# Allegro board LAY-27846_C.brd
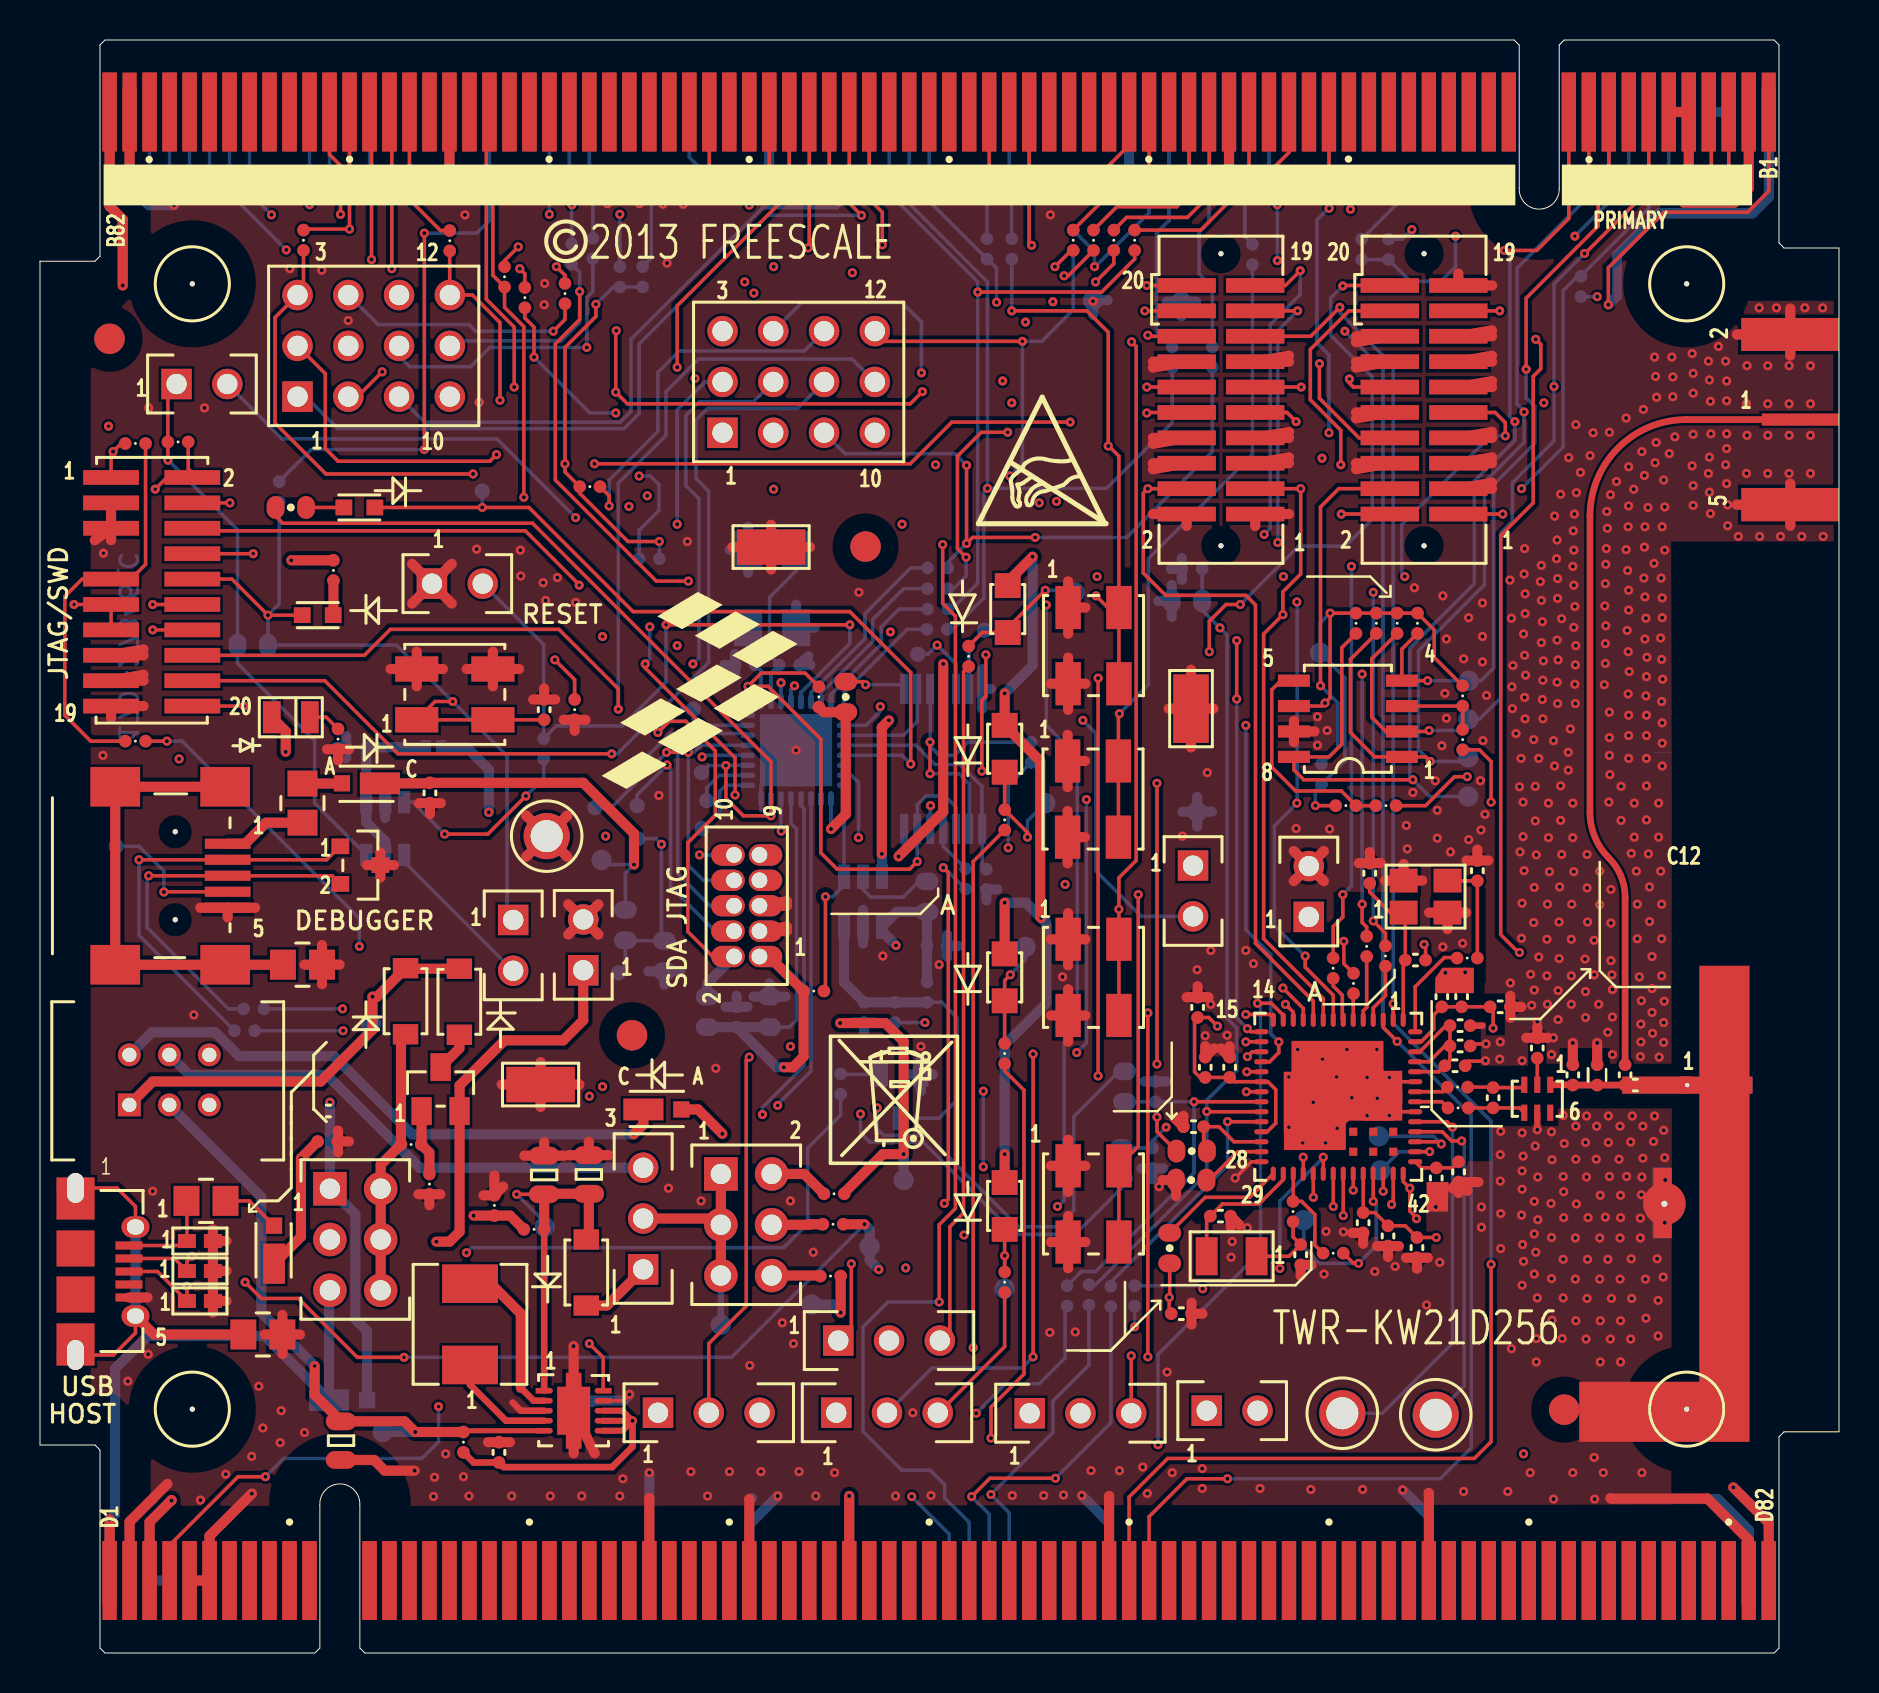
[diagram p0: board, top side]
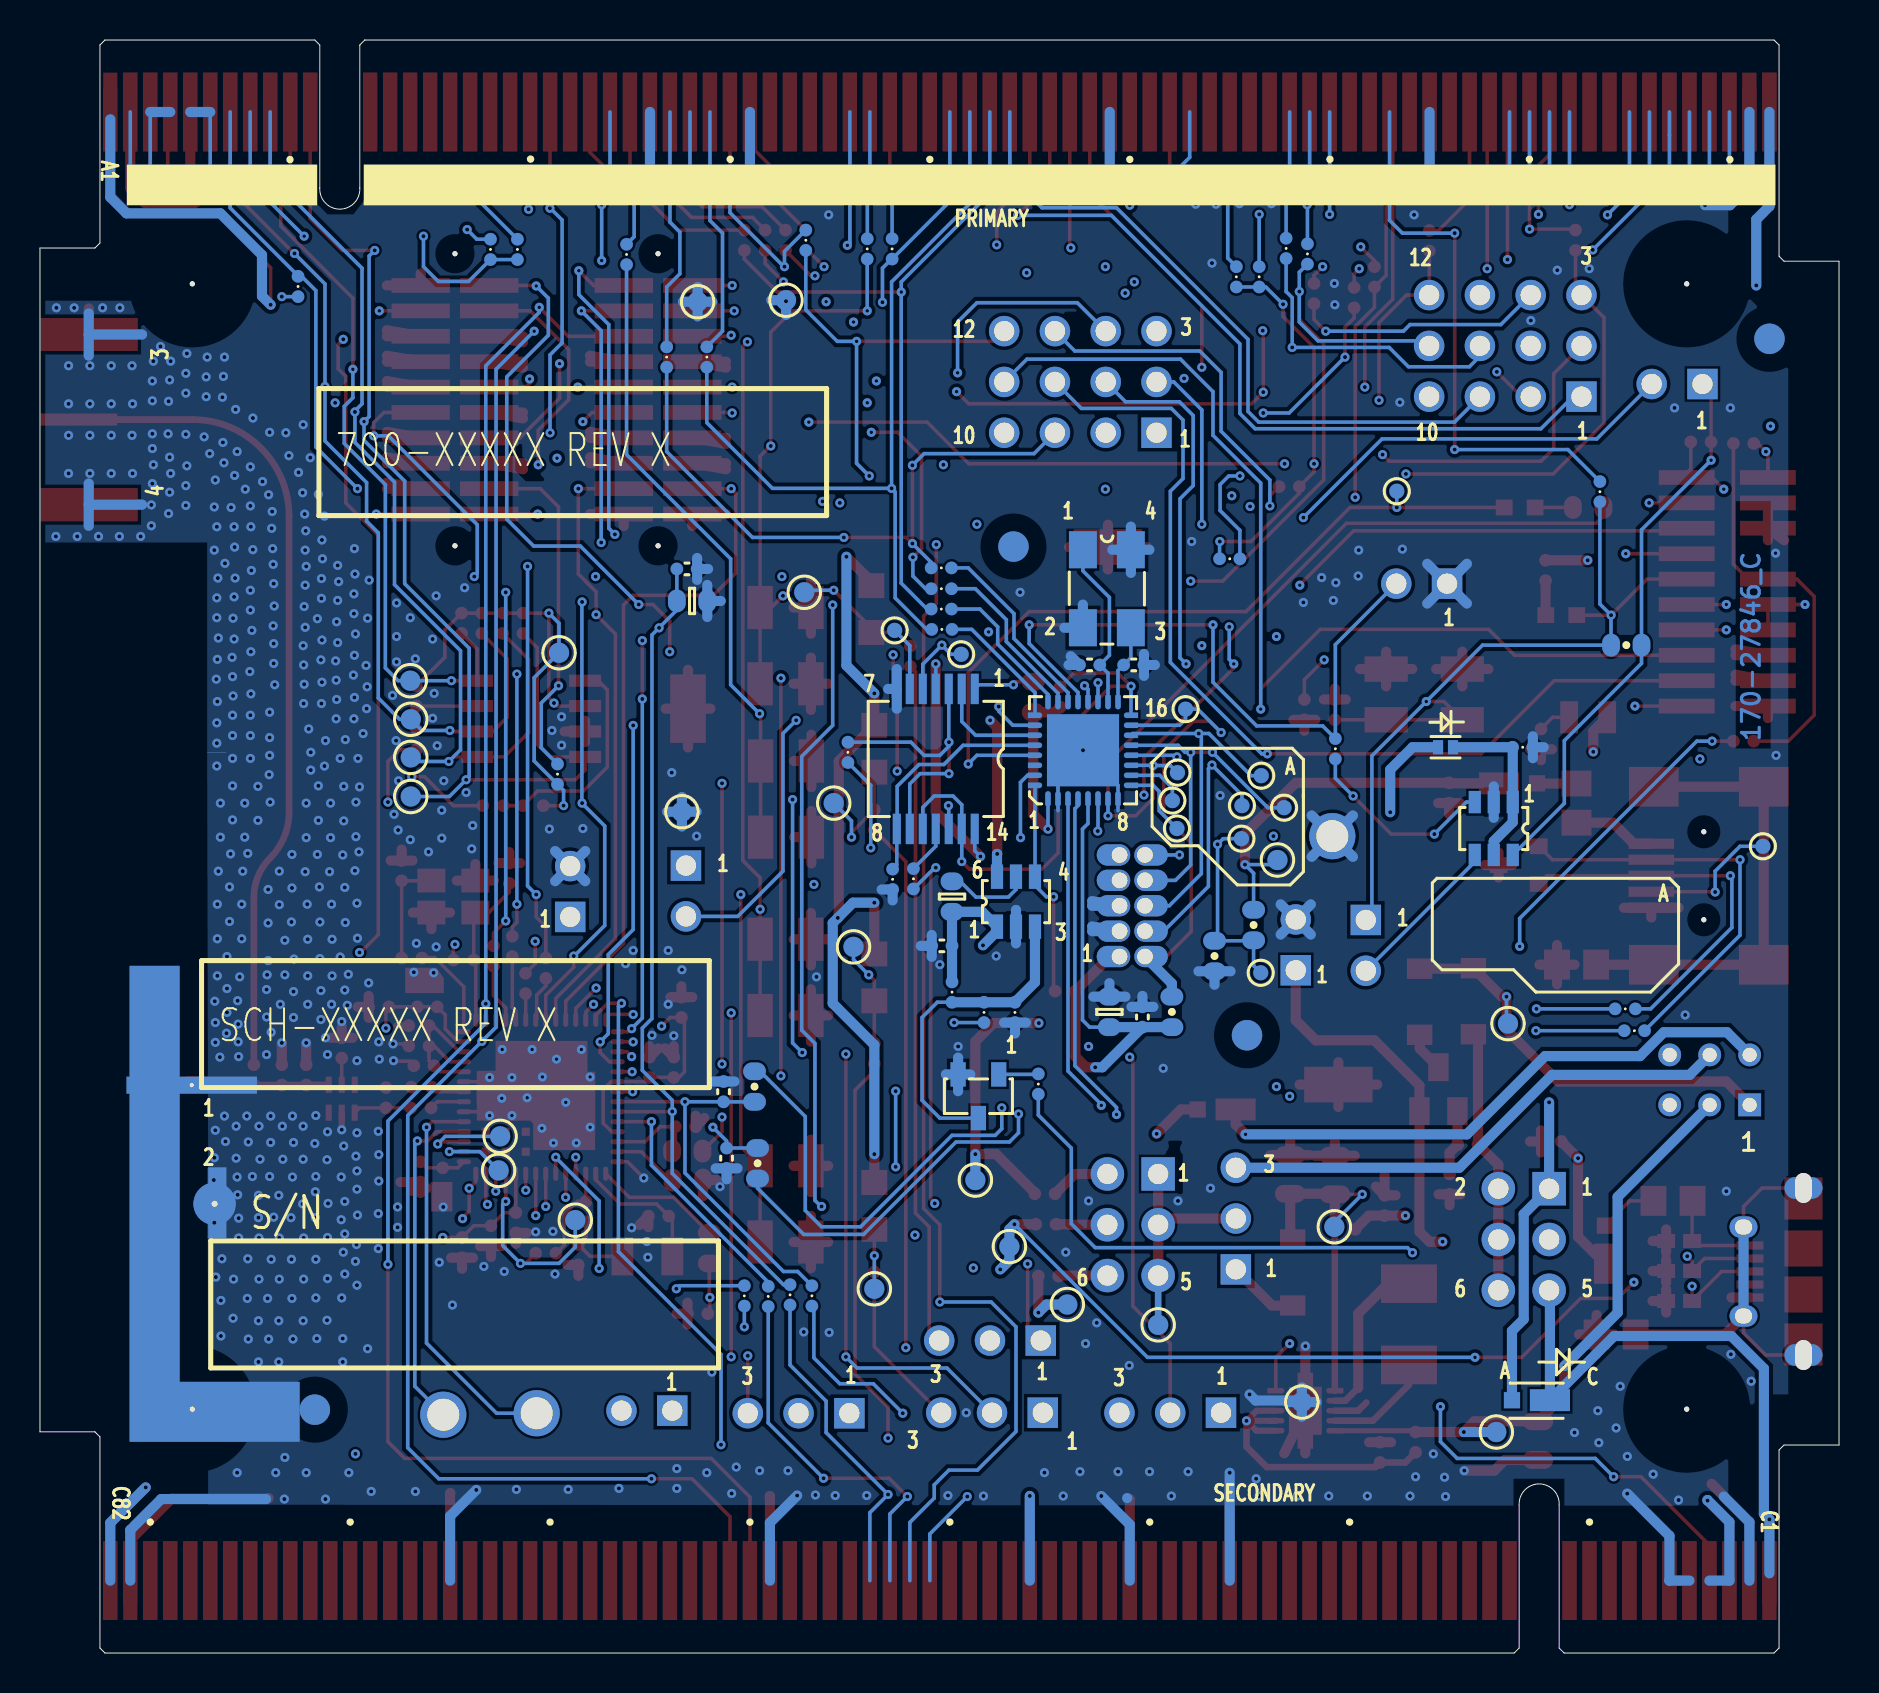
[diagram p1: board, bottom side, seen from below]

Outline 90 x 80.65 mm; copper layers: TOP, L2_GND, L3_PWR, BOTTOM. Coordinates in mm from the lower left corner of the outline.
Outline path: 0,69.59 2.75,69.59 3,69.84 3,80.4 3.25,80.65 73.75,80.65 73.75,80.65 74,80.4 74,73.25 arc(75,72.19) 76,73.25 76,80.4 76.25,80.65 86.75,80.65 87,80.4 87,70.5 87.25,70.25 90,70.25 90,11.06 87.25,11.06 87,10.81 87,0.25 86.75,0 16.25,0 16,0.25 16,7.4 arc(15,8.45) 14,7.4 14,0.25 13.75,0 3.25,0 3,0.25 3,10.15 2.75,10.4 0,10.4 0,69.59

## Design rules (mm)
net group POWER: nets V_LED

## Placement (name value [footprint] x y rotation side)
ANT1  F_Antenna  [F_ANTENNA_DIG528-2]  82.41 28.39 270 top
C1  10UF  [CC0805_OV]  15.06 10.62 270 top
C2  10UF  [CC0805_OV]  27.46 23.93 90 top
C3  10UF  [CC0805_OV]  25.22 23.9 90 top
C4  0.1UF  [CC0402_25]  22.96 10.03 90 top
C7  0.33UF  [CC0402_25]  57.91 32.28 90 top
C8  5pF  [CC0402_25]  59.51 29.29 90 top
C9  1000pF  [CC0402_25]  58.29 29.29 90 top
C10  5pF  [CC0402_25]  70.13 32.82 90 top
C11  1000pF  [CC0402_25]  71.12 32.82 90 top
C12  0.1UF  [CC0402_25]  73.05 32.31 0 top
C13  0.1UF  [CC0402_25]  57.1 16.97 0 top
C14  0.1UF  [CC0402_25]  68.88 20.27 270 top
C15  33PF  [CC0402_25]  70.97 24.05 270 top
C16  0.33UF  [CC0402_25]  69.85 23.75 270 top
C17  10PF  [CC0402_25]  79.3 28.91 90 top
C18  10PF  [CC0402_25]  79.81 28.4 180 top
C19  1.8pF  [CC0402_25]  76.68 28.91 90 top
C20  10PF  [CC0402_25]  68.81 34.65 180 top
C21  12PF  [CC0402_25]  66.52 38.99 90 top
C22  12PF  [CC0402_25]  71.91 39.12 90 top
C23  12PF  [CC0402_25]  63.07 19.91 270 top
C24  12PF  [CC0402_25]  59.05 21.84 0 top
C25  1PF  [CC0402_25]  72.69 27.76 90 top
C26  1.0UF  [CC0402_25]  34.85 31.8 90 bottom
C27  2.2UF  [CC0603_OV]  57.38 52.6 180 bottom
C28  0.1UF  [CC0402_25]  57.63 54.2 180 bottom
C29  0.1UF  [CC0402_25]  25.22 47.17 90 top
C30  22PF  [CC0402_25]  37.49 49.4 0 bottom
C31  22PF  [CC0402_25]  35.28 49.4 180 bottom
C32  2.2UF  [CC0603_OV]  36.5 32.05 90 bottom
C33  0.1UF  [CC0402_25]  44.88 35.36 0 bottom
C34  18PF  [CC0603_OV]  44.37 37.82 90 bottom
C35  47PF  [CC0402_25]  55.8 28.07 90 bottom
C36  0.1UF  [CC0402_25]  57.71 26.31 180 top
C42  0.1UF  [CC0402_25]  71.04 31.37 0 top
C43  1000pF  [CC0402_25]  71.04 30.35 0 top
C44  5pF  [CC0402_25]  70.79 29.36 0 top
C45  10PF  [CC0402_25]  74.9 30.25 90 top
C46  1000pF  [CC0402_25]  67.44 20.85 270 top
C47  5pF  [CC0402_25]  66.19 21.51 270 top
C48  47PF  [CC0402_25]  55.65 24.74 270 bottom
C49  1.0UF  [CC0402_25]  19.51 43 270 top
C50  1.0UF  [CC0402_25]  14.4 25.58 0 top
D1  MBR0520LT1G  [SOD123]  18.29 32.59 270 top
D2  MBR0520LT1G  [SOD123]  27.33 19.02 90 top
D3  MBR0520LT1G  [SOD123]  20.98 32.56 270 top
D4  GREEN  [LED0805]  12.55 46.79 270 top
D5  BLUE  [LED2_2P34_2P1X1P25]  48.26 22.35 90 top
D6  BLUE  [LED2_2P34_2P1X1P25]  48.26 33.78 90 top
D7  BLUE  [LED2_2P34_2P1X1P25]  48.26 45.21 90 top
D8  BLUE  [LED2_2P34_2P1X1P25]  48.41 52.2 90 top
D9  ORANGE  [LED_0603]  13.89 51.89 180 top
D11  LED GREEN  [LED_0603]  15.98 57.28 0 top
D12  MSS1P3L  [SMB_2P7X1P4]  15.11 12.64 0 bottom
D13  MSS1P3L  [SMB_2P7X1P4]  16.36 43.48 180 top
D14  MSS1P3L  [SMB_2P7X1P4]  30.84 27.18 0 top
D15  MSS1P3L  [SMB_2P7X1P4]  11.71 20.12 90 top
D16  CDSQR400B  [SOD-923F]  19.68 45.29 0 bottom
J1  HDR 2X3  [HDR203]  14.5 23.22 0 top
J2  HDR 2X3  [HDR203]  34.06 23.95 0 top
J3  HDR TH 1X3  [HDR103]  30.18 19.18 180 top
J4  SMA  [CON_SMA_EDGE_062]  88.07 61.67 90 top
J5  HDR 1X2  [HDR102]  63.47 36.8 180 top
J6  MICRO USB AB 5  [CON5_MICROUSB]  1.78 19.08 270 top
J8  HDR 1X2 TH  [HDR102]  6.83 63.45 90 top
J9  CON_2X10  [CON_TFM_20M_50_SM]  69.24 62.66 180 top
J10  CON_2X10  [CON_TFM_20M_50_SM]  59.08 62.66 180 top
J11  HDR_19P  [CON_FTSH_19M_50_SM]  5.59 53.06 0 top
J12  HDR 1X2 TH  [HDR102]  57.68 39.37 0 top
J13  HDR 2X5  [CON_2RH_10_50]  35.99 34.82 90 top
J15  CONN USB MINI-B  [CON5_USB_RA_SMT]  5.74 38.86 0 top
J16  PCI EXPRESS TOWER SYSTEM  [CN2X82_FINGER_ASS]  2.98 14.78 0 top
J17  HDR 3X4  [HDR304]  12.88 62.82 90 top
J18  HDR 3X4  [HDR304]  34.14 61.01 90 top
J19  HDR TH 1X3  [HDR103]  39.83 12.01 90 top
J20  HDR TH 1X3  [HDR103]  30.92 12.01 90 top
J21  HDR TH 1X3  [HDR103]  49.51 11.99 90 top
J24  HDR TH 1X3  [HDR103]  39.94 15.62 90 top
J27  HDR 1X2 TH  [HDR102]  58.37 12.12 90 top
J28  HDR 1X2  [HDR102]  27.18 34.14 180 top
J29  HDR 1X2  [HDR102]  23.67 36.65 0 top
J30  HDR 1X2  [HDR102]  19.61 53.47 90 top
L1  3.3uH  [IND_IHLP_2020]  21.51 16.43 90 top
L2  0  [RC0603_OV]  57.62 25.1 180 top
L3  0  [RC0603_OV]  57.59 23.65 180 top
L4  330 OHM  [IND_0805]  8.31 22.61 0 top
L5  2.2nH  [IND_0402]  77.9 28.91 90 top
L6  330 OHM  [IND_0805]  13.13 42.49 90 top
L7  330 OHM  [IND_0805]  13.13 34.42 0 top
L8  330 OHM  [IND_0805]  11.15 15.93 0 top
NOREF  -  []  5.08 15.98 0 top
NOREF#2  -  [unnamed#2]  3.48 65.71 0 top
NOREF#3  -  []  -22.3 31.52 0 top
NOREF#4  -  []  59.16 40.69 0 top
NOREF#5  -  []  17.78 -31.64 0 top
NOREF#6  -  []  26.94 40.84 0 top
NOREF#7  -  []  28.55 87.45 0 top
NOREF#8  -  []  26.11 70.71 0 top
NOREF#9  -  []  19.31 45.29 0 top
NOREF#10  -  [unnamed#2]  7.62 12.19 0 top
NOREF#11  -  [unnamed#2]  29.62 30.89 0 top
NOREF#12  -  [unnamed#2]  7.62 68.46 0 top
NOREF#13  -  []  1.52 -183.36 0 top
NOREF#14  -  []  -285.75 278.24 0 top
NOREF#15  -  []  -45.59 -112.78 0 top
NOREF#16  -  []  7.62 12.19 0 top
NOREF#17  -  []  -38.48 -138.1 0 top
NOREF#18  -  []  -69.1 137.97 0 top
NOREF#19  -  []  88.93 51.66 0 top
NOREF#20  -  []  -43.23 -166.45 0 top
NOREF#21  -  []  19.17 44.92 0 top
NOREF#22  -  []  20.21 45.61 90 top
NOREF#23  -  [unnamed#2]  41.3 55.32 0 top
NOREF#24  -  []  66.74 11.99 0 top
NOREF#25  -  []  82.22 23.34 0 top
NOREF#26  -  []  28.63 125.43 0 top
NOREF#27  -  [unnamed#2]  76.25 12.17 0 top
NOREF#28  -  [unnamed#2]  82.38 12.19 0 top
NOREF#29  -  []  -29.26 -168.66 0 top
NOREF#30  -  []  307.34 -37.36 0 top
NOREF#31  -  []  28.12 43.15 0 top
NOREF#32  -  []  -309.88 -247.54 0 top
NOREF#33  -  []  7.62 12.19 0 top
NOREF#34  -  [unnamed#2]  82.38 68.46 0 top
NOREF#35  -  []  71.41 11.91 0 top
NOREF#36  -  [unnamed#2]  29.62 30.89 180 bottom
NOREF#37  -  [unnamed#2]  3.48 65.71 180 bottom
NOREF#38  -  [unnamed#2]  76.25 12.17 180 bottom
NOREF#39  -  [unnamed#2]  41.3 55.32 180 bottom
NOREF#40  -  []  76.05 56.87 180 bottom
NOREF#41  -  []  -67.31 -5.48 0 bottom
NOREF#42  -  []  81.92 28.27 180 bottom
NOREF#43  -  []  68.17 8.16 180 bottom
Q1  SI2305  [SOT-23]  20.04 28.19 0 top
Q2  MMBT2484L  [SOT23]  43.05 27.84 0 bottom
R1  0  [RC0402_25]  21.18 10.54 270 top
R2  0  [RC0402_25]  24.71 21.18 180 top
R4  0  [RC0402_25]  39.73 22.96 0 top
R5  200K  [RC0402_25]  22.73 22.38 90 top
R6  0  [RC0402_25]  39.67 21.44 0 top
R7  4.7K  [RC0402_25]  18.57 25.43 0 top
R8  0  [RC0402_25]  39.55 18.85 0 top
R9  10K  [RC0402_25]  19.48 23.44 270 top
R10  330  [RC0402_25]  14.91 45.69 270 top
R12  1.0M  [RC0603_OV]  56.52 20.24 90 top
R13  0  [RC0402_25]  70.94 27.25 0 top
R14  0  [RC0402_25]  70.92 28.3 0 top
R15  0  [RC0402_25]  71.4 34.75 0 top
R16  390  [RC0402_25]  48.26 18.54 270 top
R17  390  [RC0402_25]  48.26 29.97 270 top
R18  390  [RC0402_25]  48.26 41.66 270 top
R19  390  [RC0402_25]  46.46 49.83 270 top
R20  0  [RC0402_25]  64.11 43.94 270 bottom
R21  4.7K  [RC0402_25]  30.15 68.81 90 bottom
R22  4.7K  [RC0402_25]  29.01 68.81 90 bottom
R23  10.0K  [RC0402_25]  27.51 58.32 0 top
R24  10.0K  [RC0402_25]  30.48 54.71 180 bottom
R25  10.0K  [RC0402_25]  6.91 60.55 180 top
R26  10.0K  [RC0402_25]  4.78 60.48 0 top
R27  0  [RC0402_25]  4.78 45.59 180 top
R33  33  [RC0603_OV]  54.25 28.32 270 bottom
R34  33  [RC0603_OV]  54.1 24.49 90 bottom
R46  330  [RC0402_25]  14.68 54.13 270 top
R50  33  [RC0402_25]  10.24 31.11 0 bottom
R51  33  [RC0402_25]  10.69 32.21 0 bottom
R52  4.7K  [RC0603_OV]  29.29 36.4 270 bottom
R58  0  [RC0402_25]  53.72 70.64 90 top
R59  0  [RC0402_25]  58.65 64.8 270 bottom
R60  0  [RC0402_25]  51.69 70.64 90 top
R61  0  [RC0402_25]  52.7 70.64 270 top
R62  0  [RC0402_25]  56.64 64.8 270 bottom
R63  0  [RC0402_25]  51.69 70.64 90 bottom
R64  0  [RC0402_25]  47.37 70.21 90 bottom
R65  0  [RC0402_25]  54.76 70.64 90 top
R66  0  [RC0402_25]  48.62 70.21 270 bottom
R67  0  [RC0402_25]  60.66 69.93 270 bottom
R68  0  [RC0402_25]  27.66 70.23 270 bottom
R69  0  [RC0402_25]  26.59 69.95 270 bottom
R70  0  [RC0402_25]  20.5 70.61 90 top
R71  0  [RC0402_25]  24.26 67.77 90 top
R72  0  [RC0402_25]  26.26 67.97 90 top
R73  0  [RC0402_25]  13.18 70.64 90 top
R74  0  [RC0402_25]  77.09 68.33 270 bottom
R75  0  [RC0402_25]  67.46 70.18 270 bottom
R76  0  [RC0402_25]  66.12 70.18 270 bottom
R77  0  [RC0402_25]  23.24 68.81 270 top
R78  0  [RC0402_25]  67.31 34.85 270 top
R79  0  [RC0402_25]  66.37 35.33 270 top
R80  0  [RC0402_25]  65.71 33.48 270 top
R81  0  [RC0402_25]  64.69 34.24 270 top
R82  0  [RC0402_25]  62.69 22.07 90 top
R83  0  [RC0402_25]  64.69 19.99 180 top
R84  0  [RC0402_25]  54.76 17.86 90 bottom
R85  0  [RC0402_25]  51.38 17.86 90 bottom
R86  0  [RC0402_25]  52.48 17.91 90 bottom
R87  0  [RC0402_25]  53.57 17.83 90 bottom
R88  1.0K  [RC0402_25]  44.91 52.2 0 bottom
R89  1.0K  [RC0402_25]  44.88 51.18 0 bottom
R90  1.0K  [RC0402_25]  44.91 54.25 0 bottom
R91  1.0K  [RC0402_25]  44.91 53.21 0 bottom
R92  1.0K  [RC0402_25]  49.58 45.03 270 bottom
R93  1.0K  [RC0402_25]  46.3 38.71 270 bottom
R94  0  [RC0402_25]  25.2 45.21 270 bottom
R95  0  [RC0402_25]  26.75 47.17 90 top
R100  10K  [RC0603_OV]  31.24 34.85 270 bottom
R104  220  [RC0603_OV]  12.55 57.28 0 top
R105  10K  [RC0603_OV]  40.31 47.8 270 top
R106  27K  [RC0402_25]  38.96 47.8 90 top
R107  10K  [RC0603_OV]  33.38 32.05 90 bottom
R108  10.0K  [RC0402_25]  44.37 33.05 270 bottom
R109  15K  [RC0402_25]  41.22 32.03 270 bottom
R110  10.0K  [RC0402_25]  38.71 33.1 0 top
R111  1K  [RC0402_25]  40.06 28.45 90 bottom
R112  27K  [RC0402_25]  47.35 38.68 270 bottom
R551  1.0K  [RC0402_25]  42.77 32.03 90 bottom
R552  10.0K  [RC0402_25]  65.84 51.49 270 top
R553  10.0K  [RC0402_25]  68.91 51.49 270 top
R554  10.0K  [RC0402_25]  67.89 51.49 270 top
R555  10.0K  [RC0402_25]  66.85 51.49 270 top
R560  10K  [RC0603_OV]  10.64 50.39 0 bottom
R561  0  [RC0402_25]  11.96 58.06 270 bottom
R562  100K  [RC0402_25]  15.82 45.29 180 bottom
R563  10.0K  [RC0402_25]  71.17 47.85 90 top
R564  0  [RC0402_25]  71.17 45.67 270 top
R565  10.0K  [RC0402_25]  65.33 42.37 180 top
R566  0  [RC0402_25]  67.34 42.37 0 top
SW1  PB switch  [SW4_4MM]  52.7 50.37 0 top
SW2  PB switch  [SW4_4MM]  52.68 42.7 0 top
SW3  PB switch  [SW4_4MM]  52.7 33.78 0 top
SW4  PB switch  [SW4_4MM]  52.7 22.45 0 top
SW5  DPDT SWITCH  [SW_6P_11X7P31MM]  4.47 27.41 90 top
SW6  PB switch  [SW4_4MM]  20.75 47.93 90 top
TL1  TESTLOOP  [TESTPOINT_135_070MIL]  57.58 47.22 270 top
TL2  TESTLOOP  [TESTPOINT_135_070MIL]  36.58 55.3 0 top
TL3  TESTLOOP  [TESTPOINT_135_070MIL]  25.04 28.42 0 top
TP1  -  [TPAD_040]  16.56 31.47 180 bottom
TP2  -  [TPAD_040]  17.14 11.05 180 bottom
TP3  -  [TPAD_040]  25.25 21.31 180 bottom
TP4  -  [TPAD_040]  43.21 23.65 180 bottom
TP5  -  [TPAD_040]  34.06 16.41 180 bottom
TP6  -  [TPAD_040]  41.5 20.32 180 bottom
TP7  -  [TPAD_040]  38.61 17.42 180 bottom
TP9  -  [TPAD_040]  52.68 67.64 180 bottom
TP10  -  [TPAD_040]  57.1 67.56 180 bottom
TP11  -  [TPAD_040]  26.87 12.55 180 bottom
TP12  -  [TPAD_040]  57.89 42.06 180 bottom
TP14  -  [TPAD_040]  48.26 18.21 180 bottom
TP15  -  [TPAD_040]  49.3 35.31 180 bottom
TP16  -  [TPAD_040]  50.29 42.49 180 bottom
TP17  -  [TPAD_040]  51.77 53.04 180 bottom
TP21  -  [TPAD_040]  67.06 24.13 90 bottom
TP22  -  [TPAD_040]  66.98 25.83 180 bottom
TP25  TESTLOOP_BLACK  [TP_TH_063]  65.15 11.99 0 top
TP26  TESTLOOP_BLACK  [TP_TH_063]  69.82 11.91 0 top
TP27  -  [TPAD_040]  63.22 21.64 180 bottom
TP100  -  [TPAD_030]  3.81 40.34 180 bottom
TP101  -  [TPAD_030]  33.12 41.22 180 bottom
TP102  -  [TPAD_030]  33.35 42.62 180 bottom
TP103  -  [TPAD_030]  33.1 44.02 180 bottom
TP104  -  [TPAD_040]  28.09 39.65 180 bottom
TP105  -  [TPAD_030]  28.93 34.01 180 bottom
TP106  -  [TPAD_030]  22.12 58.09 180 bottom
TP107  -  [TPAD_030]  43.92 49.94 180 bottom
TP108  -  [TPAD_030]  47.24 51.13 180 bottom
TP500  -  [TPAD_040]  71.45 44.78 0 bottom
TP501  -  [TPAD_040]  71.45 42.82 0 bottom
TP502  -  [TPAD_040]  64.03 50.01 0 bottom
TP504  -  [TPAD_040]  71.45 46.69 0 bottom
TP506  -  [TPAD_040]  71.48 48.62 0 bottom
TP507  TESTLOOP_BLACK  [TP_TH_063]  25.35 40.84 0 top
TP508  -  [TPAD_030]  32.69 47.19 180 bottom
TP509  -  [TPAD_030]  29.87 42.37 180 bottom
TP510  -  [TPAD_030]  28.91 43.87 180 bottom
TP511  -  [TPAD_030]  27.76 42.27 180 bottom
TP512  -  [TPAD_030]  29.9 40.72 180 bottom
U1  TPS63001  [QFN_10_0P5_3X3]  26.7 12.11 0 top
U3  MKW21D256V  [LGA63_0P5_8X8]  64.95 27.81 270 top
U4  74LVC125ADB  [SSOP14]  45.19 44.7 270 bottom
U6  PK20DX128VFM5  [QFN32_S142EP]  37.82 45.14 90 bottom
U7  MIC2005-0.8YM6  [SOT23-6_A]  41.17 37.57 90 bottom
U8  GSOT05C-GS08  [SOT23_A]  16.03 39.4 270 top
U10  0402ESDA-MLP  [0402_MLP]  8 20.6 0 top
U11  0402ESDA-MLP  [0402_MLP]  8 19.1 0 top
U12  0402ESDA-MLP  [0402_MLP]  8 17.6 0 top
U13  AT45DB161E-SSHD  [SO8_1P27_4X5]  65.43 46.71 180 top
U14  TXS0101  [SOT23-6]  17.27 41.22 0 bottom
Y1  32MHZ  [XTLOSC4_3P2X2P5MM_SM]  69.32 37.82 0 top
Y2  32.768KHZ  [XTAL2-3P2X1P5-SM]  59.61 19.84 180 top
Y3  8MHZ  [XTLOSC4_5X3MM_SM]  36.63 53.21 270 bottom
Z1  2400MHz 50OHM  [XFMR_HHM1525_2X1_25MM_6P]  74.9 27.71 180 top

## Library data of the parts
ANT1 = F_Antenna
C1-C4 C7-C16 C19 C21-C26 C29-C32 C36 C42-C47 C49 C50 = CAP_NP
C17 C18 C20 C34 C35 C48 = CAP_NP: tolerance: 5%
C27 C28 C33 = CAP_NP: tolerance: 10%
D1-D3 D12-D15 = DIODE_SCHTKY
D4-D9 D11 = LED
D16 = DIODE
J1 J2 = CONN_HDR_3X2
J3 J19-J21 J24 = CONN_HDR_3X1
J4 = SMB
J5 J8 J12 J27-J30 = CONN_HDR_2X1
J6 J15 = USB_MINI_AB_RECEPTACLE
J9 J10 = CONN_SHRHDR_10X2
J11 = CONN_HDR_19
J13 = CONN_HDR_5X2: User Part Number: 210-07961-00
J16 = CONN_PCI_XPRESS_X16_328P
J17 J18 = HDR_3X4
L1 L5 = INDUCTOR
L2 L3 R1 R2 R4-R10 R13-R22 R27 R50-R52 R58-R87 R94 R95 R100 R104-R107 R112 R560-R562 R564 R566 = RES
L4 L6 L7 = BEAD
L8 = BEAD: tolerance: 25%
Q1 = MOSFET_P
Q2 = NPN
R12 R33 R34 R111 = RES: tolerance: 5%
R23-R26 R46 R88-R93 R108-R110 R551 = RES: tolerance: 1%
R552-R555 R563 R565 = RES: tolerance: 1%; signal model: DEFAULT_RESISTOR_10000OHM_2_1
SW1-SW4 SW6 = SW_TACT-SPST-2_SM
SW5 = SW_6P
TL1-TL3 TP1-TP7 TP9-TP12 TP14-TP17 TP21 TP22 TP25-TP27 TP104 TP507 = TestLoop
TP100-TP103 TP105-TP108 TP500-TP502 TP504 TP506 TP508-TP512 = TESTLOOP
U1 = tps63001
U3 = MKW21D_LGA_63P
U4 = 74-125_14P
U6 = PK20DX128V_QFN_32P
U7 = MIC2005-0.8YM6
U8 = DIODE_2LINE_ESD
U10-U12 = DIODE_TVS_BIDIR
U13 = AT45DB041D-SU
U14 = TXB0101_6P
Y1 = XTAL_13Y
Y2 = CRYSTAL
Y3 = CRYSTAL_JXS63
Z1 = LDB_21

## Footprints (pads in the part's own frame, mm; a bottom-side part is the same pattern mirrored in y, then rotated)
0402_MLP
  rect 0.9x0.7 smd: 1(-0.65,0) 2(0.65,0)
CC0402_25
  round 0.635 smd: 1(-0.508,0) 2(0.508,0)
CC0603_OV
  oval 0.889x1.143 smd: 1(-0.762,0) 2(0.762,0)
CC0805_OV
  oval 0.889x1.524 smd: 1(-0.965,0) 2(0.965,0)
CN2X82_FINGER_ASS
  rect 0.711x3.2 smd: A1(83.499,61.9) B81(1.499,61.9) C1(0.499,-10.795) D81(82.499,-10.795)
  rect 0.711x3.937 smd: A2(82.499,62.268) A3(81.499,62.268) A4(80.499,62.268) A5(79.499,62.268) A6(78.499,62.268) A7(77.499,62.268) A8(76.499,62.268) A9(75.499,62.268) A10(74.499,62.268) A11(73.499,62.268) A12(70.499,62.268) A13(69.499,62.268) A14(68.499,62.268) A15(67.499,62.268) A16(66.499,62.268) A17(65.499,62.268) A18(64.499,62.268) A19(63.499,62.268) A20(62.499,62.268) A21(61.499,62.268) A22(60.499,62.268) A23(59.499,62.268) A24(58.499,62.268) A25(57.499,62.268) A26(56.499,62.268) A27(55.499,62.268) A28(54.499,62.268) A29(53.499,62.268) A30(52.499,62.268) A31(51.499,62.268) A32(50.499,62.268) A33(49.499,62.268) A34(48.499,62.268) A35(47.499,62.268) A36(46.499,62.268) A37(45.499,62.268) A38(44.499,62.268) A39(43.499,62.268) A40(42.499,62.268) A41(41.499,62.268) A42(40.499,62.268) A43(39.499,62.268) A44(38.499,62.268) A45(37.499,62.268) A46(36.499,62.268) A47(35.499,62.268) A48(34.499,62.268) A49(33.499,62.268) A50(32.499,62.268) A51(31.499,62.268) A52(30.499,62.268) A53(29.499,62.268) A54(28.499,62.268) A55(27.499,62.268) A56(26.499,62.268) A57(25.499,62.268) A58(24.499,62.268) A59(23.499,62.268) A60(22.499,62.268) A61(21.499,62.268) A62(20.499,62.268) A63(19.499,62.268) A64(18.499,62.268) A65(17.499,62.268) A66(16.499,62.268) A67(15.499,62.268) A68(14.499,62.268) A69(13.499,62.268) A70(12.499,62.268) A71(11.499,62.268) A72(10.499,62.268) A73(9.499,62.268) A74(8.499,62.268) A75(7.499,62.268) A76(6.499,62.268) A77(5.499,62.268) A78(4.499,62.268) A79(3.499,62.268) A80(2.499,62.268) A81(1.499,62.268) A82(0.499,62.268) B1(83.499,62.268) B2(82.499,62.268) B3(81.499,62.268) B4(80.499,62.268) B5(79.499,62.268) B6(78.499,62.268) B7(77.499,62.268) B8(76.499,62.268) B9(75.499,62.268) B10(74.499,62.268) B11(73.499,62.268) B12(70.499,62.268) B13(69.499,62.268) B14(68.499,62.268) B15(67.499,62.268) B16(66.499,62.268) B17(65.499,62.268) B18(64.499,62.268) B19(63.499,62.268) B20(62.499,62.268) B21(61.499,62.268) B22(60.499,62.268) B23(59.499,62.268) B24(58.499,62.268) B25(57.499,62.268) B26(56.499,62.268) B27(55.499,62.268) B28(54.499,62.268) B29(53.499,62.268) B30(52.499,62.268) B31(51.499,62.268) B32(50.499,62.268) B33(49.499,62.268) B34(48.499,62.268) B35(47.499,62.268) B36(46.499,62.268) B37(45.499,62.268) B38(44.499,62.268) B39(43.499,62.268) B40(42.499,62.268) B41(41.499,62.268) B42(40.499,62.268) B43(39.499,62.268) B44(38.499,62.268) B45(37.499,62.268) B46(36.499,62.268) B47(35.499,62.268) B48(34.499,62.268) B49(33.499,62.268) B50(32.499,62.268) B51(31.499,62.268) B52(30.499,62.268) B53(29.499,62.268) B54(28.499,62.268) B55(27.499,62.268) B56(26.499,62.268) B57(25.499,62.268) B58(24.499,62.268) B59(23.499,62.268) B60(22.499,62.268) B61(21.499,62.268) B62(20.499,62.268) B63(19.499,62.268) B64(18.499,62.268) B65(17.499,62.268) B66(16.499,62.268) B67(15.499,62.268) B68(14.499,62.268) B69(13.499,62.268) B70(12.499,62.268) B71(11.499,62.268) B72(10.499,62.268) B73(9.499,62.268) B74(8.499,62.268) B75(7.499,62.268) B76(6.499,62.268) B77(5.499,62.268) B78(4.499,62.268) B79(3.499,62.268) B80(2.499,62.268) B82(0.499,62.268) C2(1.499,-11.163) C3(2.499,-11.163) C4(3.499,-11.163) C5(4.499,-11.163) C6(5.499,-11.163) C7(6.499,-11.163) C8(7.499,-11.163) C9(8.499,-11.163) C10(9.499,-11.163) C11(10.499,-11.163) C12(13.499,-11.163) C13(14.499,-11.163) C14(15.499,-11.163) C15(16.499,-11.163) C16(17.499,-11.163) C17(18.499,-11.163) C18(19.499,-11.163) C19(20.499,-11.163) C20(21.499,-11.163) C21(22.499,-11.163) C22(23.499,-11.163) C23(24.499,-11.163) C24(25.499,-11.163) C25(26.499,-11.163) C26(27.499,-11.163) C27(28.499,-11.163) C28(29.499,-11.163) C29(30.499,-11.163) C30(31.499,-11.163) C31(32.499,-11.163) C32(33.499,-11.163) C33(34.499,-11.163) C34(35.499,-11.163) C35(36.499,-11.163) C36(37.499,-11.163) C37(38.499,-11.163) C38(39.499,-11.163) C39(40.499,-11.163) C40(41.499,-11.163) C41(42.499,-11.163) C42(43.499,-11.163) C43(44.499,-11.163) C44(45.499,-11.163) C45(46.499,-11.163) C46(47.499,-11.163) C47(48.499,-11.163) C48(49.499,-11.163) C49(50.499,-11.163) C50(51.499,-11.163) C51(52.499,-11.163) C52(53.499,-11.163) C53(54.499,-11.163) C54(55.499,-11.163) C55(56.499,-11.163) C56(57.499,-11.163) C57(58.499,-11.163) C58(59.499,-11.163) C59(60.499,-11.163) C60(61.499,-11.163) C61(62.499,-11.163) C62(63.499,-11.163) C63(64.499,-11.163) C64(65.499,-11.163) C65(66.499,-11.163) C66(67.499,-11.163) C67(68.499,-11.163) C68(69.499,-11.163) C69(70.499,-11.163) C70(71.499,-11.163) C71(72.499,-11.163) C72(73.499,-11.163) C73(74.499,-11.163) C74(75.499,-11.163) C75(76.499,-11.163) C76(77.499,-11.163) C77(78.499,-11.163) C78(79.499,-11.163) C79(80.499,-11.163) C80(81.499,-11.163) C81(82.499,-11.163) C82(83.499,-11.163) D1(0.499,-11.163) D2(1.499,-11.163) D3(2.499,-11.163) D4(3.499,-11.163) D5(4.499,-11.163) D6(5.499,-11.163) D7(6.499,-11.163) D8(7.499,-11.163) D9(8.499,-11.163) D10(9.499,-11.163) D11(10.499,-11.163) D12(13.499,-11.163) D13(14.499,-11.163) D14(15.499,-11.163) D15(16.499,-11.163) D16(17.499,-11.163) D17(18.499,-11.163) D18(19.499,-11.163) D19(20.499,-11.163) D20(21.499,-11.163) D21(22.499,-11.163) D22(23.499,-11.163) D23(24.499,-11.163) D24(25.499,-11.163) D25(26.499,-11.163) D26(27.499,-11.163) D27(28.499,-11.163) D28(29.499,-11.163) D29(30.499,-11.163) D30(31.499,-11.163) D31(32.499,-11.163) D32(33.499,-11.163) D33(34.499,-11.163) D34(35.499,-11.163) D35(36.499,-11.163) D36(37.499,-11.163) D37(38.499,-11.163) D38(39.499,-11.163) D39(40.499,-11.163) D40(41.499,-11.163) D41(42.499,-11.163) D42(43.499,-11.163) D43(44.499,-11.163) D44(45.499,-11.163) D45(46.499,-11.163) D46(47.499,-11.163) D47(48.499,-11.163) D48(49.499,-11.163) D49(50.499,-11.163) D50(51.499,-11.163) D51(52.499,-11.163) D52(53.499,-11.163) D53(54.499,-11.163) D54(55.499,-11.163) D55(56.499,-11.163) D56(57.499,-11.163) D57(58.499,-11.163) D58(59.499,-11.163) D59(60.499,-11.163) D60(61.499,-11.163) D61(62.499,-11.163) D62(63.499,-11.163) D63(64.499,-11.163) D64(65.499,-11.163) D65(66.499,-11.163) D66(67.499,-11.163) D67(68.499,-11.163) D68(69.499,-11.163) D69(70.499,-11.163) D70(71.499,-11.163) D71(72.499,-11.163) D72(73.499,-11.163) D73(74.499,-11.163) D74(75.499,-11.163) D75(76.499,-11.163) D76(77.499,-11.163) D77(78.499,-11.163) D78(79.499,-11.163) D79(80.499,-11.163) D80(81.499,-11.163) D82(83.499,-11.163)
CON5_MICROUSB
  rect 1.803x1.905 smd: (-1.15,0) (1.15,0)
  rect 0.406x1.346 smd: 1(-1.3,2.675) 2(-0.65,2.675) 3(0,2.675) 4(0.65,2.675) 5(1.3,2.675)
  oval 1.067x1.397 hole 0.762x0.864: S1(-2.225,3) S2(2.225,3)
  rect 2.108x1.905 hole 1.499x0.838: S3(-4.175,0) S4(4.175,0)
CON5_USB_RA_SMT
  round 0.254 hole 0.889 unplated: (1.025,2.2) (1.025,-2.2)
  rect 2.286x0.508 smd: 1(3.65,1.6) 2(3.65,0.8) 3(3.65,0) 4(3.65,-0.8) 5(3.65,-1.6)
  rect 2.489x1.981 smd: S1(3.525,4.45) S2(3.525,-4.45) S3(-1.975,4.45) S4(-1.975,-4.45)
CON_2RH_10_50
  oval 1.067x1.676 hole 0.787: 1(0,0) 2(0,1.27) 3(1.27,0) 4(1.27,1.27) 5(2.54,0) 6(2.54,1.27) 7(3.81,0) 8(3.81,1.27) 9(5.08,0) 10(5.08,1.27)
CON_FTSH_19M_50_SM
  rect 2.794x0.737 smd: 1(-2.032,5.715) 2(2.032,5.715) 3(-2.032,4.445) 4(2.032,4.445) 5(-2.032,3.175) 6(2.032,3.175) 8(2.032,1.905) 9(-2.032,0.635) 10(2.032,0.635) 11(-2.032,-0.635) 12(2.032,-0.635) 13(-2.032,-1.905) 14(2.032,-1.905) 15(-2.032,-3.175) 16(2.032,-3.175) 17(-2.032,-4.445) 18(2.032,-4.445) 19(-2.032,-5.715) 20(2.032,-5.715)
CON_SMA_EDGE_062
  rect 0.61x3.861 smd: 1(0,0)
  rect 1.651x4.877 smd: 2(4.255,0.508) 3(4.255,0.508) 4(-4.255,0.508) 5(-4.255,0.508)
CON_TFM_20M_50_SM
  round 0.254 hole 1.346 unplated: (0,7.303) (0,-7.303)
  rect 2.921x0.737 smd: 1(-1.714,5.715) 2(1.714,5.715) 3(-1.714,4.445) 4(1.714,4.445) 5(-1.714,3.175) 6(1.714,3.175) 7(-1.714,1.905) 8(1.714,1.905) 9(-1.714,0.635) 10(1.714,0.635) 11(-1.714,-0.635) 12(1.714,-0.635) 13(-1.714,-1.905) 14(1.714,-1.905) 15(-1.714,-3.175) 16(1.714,-3.175) 17(-1.714,-4.445) 18(1.714,-4.445) 19(-1.714,-5.715) 20(1.714,-5.715)
F_ANTENNA_DIG528-2
  custom 0.212x0.212 hole 0.305: 1(0,0)
  custom 2.127x2.127 hole 0.305: 2(5.933,-1.144)
HDR102
  rect 1.524x1.524 hole 1.016: 1(0,0)
  round 1.524 hole 1.016: 2(0,-2.54)
HDR103
  rect 1.524x1.524 hole 1.016: 1(0,0)
  round 1.524 hole 1.016: 2(0,-2.54) 3(0,-5.08)
HDR203
  rect 1.676x1.676 hole 1.016: 1(0,0)
  round 1.676 hole 1.016: 2(2.54,0) 3(0,-2.54) 4(2.54,-2.54) 5(0,-5.08) 6(2.54,-5.08)
HDR304
  rect 1.524x1.524 hole 1.016: 1(0,0)
  round 1.524 hole 1.016: 2(2.54,0) 3(5.08,0) 4(0,-2.54) 5(2.54,-2.54) 6(5.08,-2.54) 7(0,-5.08) 8(2.54,-5.08) 9(5.08,-5.08) 10(0,-7.62) 11(2.54,-7.62) 12(5.08,-7.62)
IND_0402
  round 0.635 smd: 1(-0.508,0) 2(0.508,0)
IND_0805
  rect 1.295x1.499 smd: 1(-0.978,0) 2(0.978,0)
IND_IHLP_2020
  rect 1.93x2.794 smd: 1(-2.032,0) 2(2.032,0)
LED2_2P34_2P1X1P25
  rect 1.245x1.295 smd: A(1.172,0) C(-1.172,0)
LED0805
  rect 1.6x0.889 smd: A(0,-0.953) C(0,0.953)
LED_0603
  rect 0.838x0.787 smd: A(-0.775,0) C(0.775,0)
LGA63_0P5_8X8
  oval 0.711x0.254 smd: 1(-3.848,3.25) 2(-3.848,2.75) 3(-3.848,2.25) 4(-3.848,1.75) 5(-3.848,1.25) 6(-3.848,0.75) 7(-3.848,0.25) 8(-3.848,-0.25) 9(-3.848,-0.75) 10(-3.848,-1.25) 11(-3.848,-1.75) 12(-3.848,-2.25) 13(-3.848,-2.75) 14(-3.848,-3.25) 29(3.848,-3.25) 30(3.848,-2.75) 31(3.848,-2.25) 32(3.848,-1.75) 33(3.848,-1.25) 34(3.848,-0.75) 35(3.848,-0.25) 36(3.848,0.25) 37(3.848,0.75) 38(3.848,1.25) 39(3.848,1.75) 40(3.848,2.25) 41(3.848,2.75) 42(3.848,3.25)
  oval 0.254x0.711 smd: 15(-3.25,-3.848) 16(-2.75,-3.848) 17(-2.25,-3.848) 18(-1.75,-3.848) 19(-1.25,-3.848) 20(-0.75,-3.848) 21(-0.25,-3.848) 22(0.25,-3.848) 23(0.75,-3.848) 24(1.25,-3.848) 25(1.75,-3.848) 26(2.25,-3.848) 27(2.75,-3.848) 28(3.25,-3.848) 43(3.25,3.848) 44(2.75,3.848) 45(2.25,3.848) 46(1.75,3.848) 47(1.25,3.848) 48(0.75,3.848) 49(0.25,3.848) 50(-0.25,3.848) 51(-0.75,3.848) 52(-1.25,3.848) 53(-1.75,3.848) 54(-2.25,3.848) 55(-2.75,3.848) 56(-3.25,3.848)
  rect 0.406x0.406 smd: 57(1.75,2.75) 58(2.75,2.75) 59(1.75,1.75) 60(2.75,1.75) 61(1.75,0.75) 62(2.75,0.75)
  rect 0.66x0.406 smd: 63(0,3)
  custom 0.4x0.4 smd: 64(0,2)
  rect 3.048x2.946 smd: 65(0.28,-1.25)
QFN32_S142EP
  custom 0.07x0.07 smd: 1(-2.4,1.751) 2(-2.4,1.251) 3(-2.4,0.751) 4(-2.4,0.25) 5(-2.4,-0.25) 6(-2.4,-0.751) 7(-2.4,-1.251) 8(-2.4,-1.751) 9(-1.751,-2.4) 10(-1.251,-2.4) 11(-0.751,-2.4) 12(-0.25,-2.4) 13(0.25,-2.4) 14(0.751,-2.4) 15(1.251,-2.4) 16(1.751,-2.4) 17(2.4,-1.751) 18(2.4,-1.251) 19(2.4,-0.751) 20(2.4,-0.25) 21(2.4,0.25) 22(2.4,0.751) 23(2.4,1.251) 24(2.4,1.751) 25(1.751,2.4) 26(1.251,2.4) 27(0.751,2.4) 28(0.25,2.4) 29(-0.25,2.4) 30(-0.751,2.4) 31(-1.251,2.4) 32(-1.751,2.4)
  rect 3.607x3.607 smd: 33(0,0)
QFN_10_0P5_3X3
  custom 0.07x0.07 smd: 1(-1.475,1) 2(-1.475,0.5) 3(-1.475,0) 4(-1.475,-0.5) 5(-1.475,-1) 6(1.475,-1) 7(1.475,-0.5) 8(1.475,0) 9(1.475,0.5) 10(1.475,1)
  custom 0.412x0.412 smd: 11(0,0)
RC0402_25
  round 0.635 smd: 1(-0.508,0) 2(0.508,0)
RC0603_OV
  oval 0.889x1.143 smd: 1(-0.762,0) 2(0.762,0)
SMB_2P7X1P4
  rect 0.813x0.813 smd: A(1.25,0)
  rect 2.007x1.092 smd: C(-0.65,0)
SO8_1P27_4X5
  rect 1.6x0.61 smd: 1(-2.7,1.905) 2(-2.7,0.635) 3(-2.7,-0.635) 4(-2.7,-1.905) 5(2.7,-1.905) 6(2.7,-0.635) 7(2.7,0.635) 8(2.7,1.905)
SOD123
  rect 1.016x1.27 smd: A(1.651,0) C(-1.651,0)
SOD-923F
  rect 0.508x0.711 smd: A(0.375,0) C(-0.375,0)
SOT23
  rect 0.762x1.219 smd: 1(-1.016,-1.092) 2(1.016,-1.092) 3(0,1.092)
SOT23-6
  rect 0.61x1.118 smd: 1(-0.95,-1.321) 2(0,-1.321) 3(0.95,-1.321) 4(0.95,1.321) 5(0,1.321) 6(-0.95,1.321)
SOT23-6_A
  rect 1.219x0.61 smd: 1(-1.25,0.95) 2(-1.25,0) 3(-1.25,-0.95) 4(1.25,-0.95) 5(1.25,0) 6(1.25,0.95)
SOT23_A
  rect 0.787x0.889 smd: 1(-0.94,-1.003) 2(0.94,-1.003) 3(0,1.003)
SOT-23
  rect 1.016x1.397 smd: 1(-0.95,-1.1) 2(0.95,-1.1) 3(0,1.1)
SSOP14
  rect 1.524x0.406 smd: 1(-3.5,1.95) 2(-3.5,1.3) 3(-3.5,0.65) 4(-3.5,0) 5(-3.5,-0.65) 6(-3.5,-1.3) 7(-3.5,-1.95) 8(3.5,-1.95) 9(3.5,-1.3) 10(3.5,-0.65) 11(3.5,0) 12(3.5,0.65) 13(3.5,1.3) 14(3.5,1.95)
SW4_4MM
  rect 1.27x2.159 smd: 1(-1.27,1.905) 2(-1.27,-1.905) 3(1.27,1.905) 4(1.27,-1.905)
SW_6P_11X7P31MM
  rect 1.143x1.143 hole 0.711: 1(0,0)
  round 1.143 hole 0.711: 2(0,-2) 3(0,-4) 4(2.5,-4) 5(2.5,-2) 6(2.5,0)
TESTPOINT_135_070MIL
  rect 3.429x1.778 smd: 1(0,0)
TP_TH_063
  round 2.311 hole 1.6: 1(0,0)
TPAD_030
  round 0.762 smd: 1(0,0)
TPAD_040
  round 1.016 smd: 1(0,0)
unnamed#2
  round 1.524 smd: (0,0)
XFMR_HHM1525_2X1_25MM_6P
  rect 0.305x0.813 smd: 1(-0.65,-0.699) 2(0,-0.699) 3(0.65,-0.699) 4(0.65,0.699) 5(0,0.699) 6(-0.65,0.699)
XTAL2-3P2X1P5-SM
  rect 1.092x1.905 smd: 1(-1.25,0) 2(1.25,0)
XTLOSC4_3P2X2P5MM_SM
  rect 1.397x1.194 smd: 1(-1.1,-0.8) 2(1.1,-0.8) 3(1.1,0.8) 4(-1.1,0.8)
XTLOSC4_5X3MM_SM
  rect 1.854x1.397 smd: 1(-1.95,-1.2) 2(1.95,-1.2) 3(1.95,1.2) 4(-1.95,1.2)

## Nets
3V3_ELEV: J1.3(A2) J16.A3(3.3V_4) J16.A4(3.3V_5) J16.A36(3.3V_6) J16.A82(3.3V_7) J16.B3(3.3V_1) J16.B36(3.3V_2) J16.B82(3.3V_3) J16.C3(3.3V_11) J16.C4(3.3V_12) J16.C36(3.3V_13) J16.C82(3.3V_14) J16.D3(3.3V_8) J16.D36(3.3V_9) J16.D82(3.3V_10)
5V_ELEV: D12.C J1.5(A3) J9.1(A1) J16.A1(5V_2) J16.B1(5V_1) J16.C1(5V_4) J16.D1(5V_3)
GND: ANT1.2(GND) C1.2 C2.2 C3.2 C4.2 C7.2 C8.2 C9.2 C10.2 C11.2 C12.2 C13.2 C14.2 C15.2 C16.2 C19.2 C21.2 C22.2 C23.2 C24.2 C26.2 C27.2 C28.2 C29.2 C30.2 C31.2 C32.2 C33.2 C35.2 C36.2 C42.2 C43.2 C44.2 C45.2 C46.2 C47.2 C48.2 C49.2 C50.2 J4.2(SHIELD2) J4.3(SHIELD1) J4.4(SHIELD3) J4.5(SHIELD4) J5.2 J6.5(P5) J9.3(A2) J9.5(A3) J9.6(B3) J9.7(A4) J9.10(B5) J9.11(A6) J9.13(A7) J9.14(B7) J9.15(A8) J9.16(B8) J9.19(A10) J10.1(A1) J10.2(B1) J10.5(A3) J10.6(B3) J10.7(A4) J10.8(B4) J10.13(A7) J10.14(B7) J11.3(A2) J11.5(A3) J11.15(A8) J11.17(A9) J11.19(A10) J13.3(A2) J13.5(A3) J15.5(P5) J16.A2(GND_9) J16.A5(GND_10) J16.A6(GND_11) J16.A26(GND_12) J16.A31(GND_13) J16.A49(GND_14) J16.A65(GND_15) J16.A81(GND_16) J16.B2(GND_1) J16.B5(GND_2) J16.B6(GND_3) J16.B26(GND_4) J16.B31(GND_5) J16.B49(GND_6) J16.B65(GND_7) J16.B81(GND_8) J16.C2(GND_25) J16.C5(GND_26) J16.C6(GND_27) J16.C26(GND_28) J16.C31(GND_29) J16.C49(GND_30) J16.C65(GND_31) J16.C81(GND_32) J16.D2(GND_17) J16.D5(GND_18) J16.D6(GND_19) J16.D26(GND_20) J16.D31(GND_21) J16.D49(GND_22) J16.D65(GND_23) J16.D81(GND_24) J28.2 J30.1 L3.2 L5.2 L7.2 L8.2 Q2.2(EMITTER) R5.2 R9.2 R10.2 R95.1 R100.2 R109.2 R112.2 R562.2 SW1.1 SW1.2 SW2.1 SW2.2 SW3.1 SW3.2 SW4.1 SW4.2 SW6.3 SW6.4 TL1.1(PIN1) TL2.1(PIN1) TL3.1(PIN1) TP9.1(PIN1) TP10.1(PIN1) TP11.1(PIN1) TP12.1(PIN1) TP507.1(PIN1) U1.3(PGND) U1.9(GND) U1.11(PPAD) U3.28(VSSA) U3.48(GND_PA#48) U3.51(GND_PA#51) U3.63(NC_63) U3.64(EP_GND1) U3.65(EP_GND2) U4.7(GND) U6.2(VSS1) U6.8(VSSA) U6.33(EPAD) U7.2(GND) U8.3(COM_ANODE) U10.2(A2) U11.2(A2) U12.2(A2) U13.7(GND) U14.2(GND) Y1.2 Y1.4 Y3.2(GND1) Y3.4(GND2) Z1.5(CT)
P5V0_SDA_USB_CONN_VBUS: J15.1(P1) L6.1
P5V_K24_USB: J6.1(P1) L4.1 U10.1(A1)
P5V_KW24_USB: C50.1 D15.C J27.1
P5V_SDA: C33.1 C34.1 C49.1 D13.C R52.1 R108.1 TP104.1(PIN1) U6.6(VREGIN) U7.1(VIN)
P5V_USB: D12.A J1.1(A1) J12.2 U7.6(VOUT)
VCC: J2.1(A1) J2.3(A2) J2.5(A3) J3.2 TP5.1(PIN1)
VDD_IF: C42.1 C43.1 C44.1 U3.52(VDD_PA) U3.53(VDD_IF) U3.54(VDD_RF)
VDD_REGD: C15.1 C16.1 U3.43(VDD_REGD)
VDDA: J16.A46(VDDA)
VSSA: J16.A45(VSSA)
CLK_OUT: R83.1 TP27.1(PIN1) U3.39(PTA18/EXTAL0/FTM0_FLT2/FTM_CLKI)
ELE_PS_SENSE: J16.B4(ELE_PS_SENSE_1) J16.D4(ELE_PS_SENSE_2) R111.1
EXTAL_32: R82.2 R83.2 U3.31(EXTAL32)
EXTAL_32K: C23.1 R82.1 Y2.1
EXTAL_32M: C20.2 C21.1 U3.1(EXTAL_32M) Y1.1
EZP_CSR_B: J11.9(A5) R26.2 R27.2
GPIO1: J10.15(A8) J16.D50(GPIO23) U3.2(GPIO1)
GPIO2: J10.16(B8) J16.D51(GPIO24) U3.3(GPIO2)
GPT_VBRD: J8.2 J9.2(B1)
GPT_VDA: J9.4(B2) R20.1
K24_USB_SHLD: J6.S1(SHLD1) J6.S2(SHLD2) J6.S3(SHLD3) J6.S4(SHLD4) L8.1
KW24_USB_DN: J6.2(P2) R33.1 U11.1(A1)
KW24_USB_DP: J6.3(P3) R34.1 U12.1(A1)
POWER_EN: R551.1 U6.31(ADC0_SE7B/PTD6/SPI0_PCS3/UART0_)
PTA0: J11.4(B2) R93.2 U3.33(PTA0/JTAG_TCLK/SWD_CLK/EZP_CLK/)
PTA1: J11.8(B4) U3.34(PTA1/JTAG_TDI/EZP_DI/UART0_RX/F)
PTA2: J11.6(B3) U3.35(PTA2/JTAG_TDO/TRACE_SWO/EZP_DO/)
PTA3: J11.2(B1) R25.1 R92.2 U3.36(PTA3/JTAG_TMS/SWD_DIO/U\A\R\T\0)
PTA4: R27.1 U3.37(PTA4/LLWU_P3/N\M\I\/E\Z\P\_\C\S)
PTA19: R564.2 U3.40(PTA19/XTAL0/FTM1_FLT0/FTM_CLKIN)
PTB10_TWRPI: J10.11(A6) J16.B9(SDHC_D3/S\P\I\1\_\C\S\0\) J17.3(C1) R73.1 R553.2 TP506.1(PIN1) U13.4(C\S\)
PTB11_TWRPI: J10.12(B6) J16.B7(SDHC_CLK/SPI1_CLK) J17.6(C2) R72.1 R554.2 TP504.1(PIN1) U13.2(SCK)
PTB16_TWRPI: J10.10(B5) J16.B10(SDHC_CMD/SPI1_MOSI) J17.9(C3) R71.1 R555.2 TP500.1(PIN1) U13.1(SI)
PTB17_TWRPI: J10.9(A5) J16.B11(SDHC_D0/SPI1_MISO) J17.12(C4) R70.1 R552.2 TP501.1(PIN1) U13.8(SO)
PTC4: J17.2(B1) R66.2 R78.1 SW1.3 SW1.4
PTC4_A: J16.B46(S\P\I\0\_\C\S\0\) J17.1(A1)
PTC5: J17.5(B2) R67.2 R79.1 SW2.3 SW2.4
PTC5_A: J16.B48(SPI0_CLK) J17.4(A2)
PTC6: J17.8(B3) R68.2 R80.1 SW3.3 SW3.4
PTC6_A: J16.B45(SPI0_MOSI/IO0) J17.7(A3)
PTC7: J17.11(B4) R69.2 R81.1 SW4.3 SW4.4
PTC7_A: J16.B44(SPI0_MISO/IO1) J17.10(A4)
PTD1: J9.9(A5) J16.B63(EBI_ALE/E\B\I\_\C\S\1\) U3.8(PTD1/ADC0_SE5B/SPI0_SCK/U\A\R\T)
PTD2: J10.3(A2) J16.A7(I2C0_SCL) J16.A53(GPIO17) J16.B52(GPIO5/SPI0_HOLD/IO3) R21.2 R74.1 R77.2 U3.9(PTD2/LLWU_P13/SPI0_SOUT/UART2_R)
PTD3: J10.4(B2) J16.A8(I2C0_SDA) J16.A60(I2S0_DIN1) R22.2 R75.2 R76.2 U3.10(PTD3/SPI0_SIN/UART2_TX/I2C_SCL/)
PTD4: J16.B47(S\P\I\0\_\C\S\1\) J19.2 U3.11(PTD4/LLWU_P14/MADC0_SE21/SPI0_P)
PTD4_LED: J19.3 R16.2
PTD4_TWR: J16.A78(EBI_AD2) J19.1
PTD5: J20.2 U3.12(PTD5/ADC0_SE6B/SPI0_PCS2/U\A\R\)
PTD5_LED: J20.3 R17.2
PTD5_TWR: J16.A79(EBI_AD1) J20.1
PTD6: J21.2 U3.13(PTD6/LLWU_P15/ADC0_SE7B/SPI0_PC)
PTD6_LED: J21.3 R18.2
PTD6_TWR: J16.A41(UART0_RX) J16.A80(EBI_AD0) J21.1 R64.1
PTD7: J24.2 U3.14(PTD7/MADC0_SE22/CMT_IRO/UART0_T)
PTD7_LED: J24.3 R19.2
PTD7_TWR: J16.A42(UART0_TX) J24.1
PTE0: J11.12(B6) J18.2(B1) R58.1 U3.15(PTE0/MADC0_SE10/SPI1_PCS1/UART1)
PTE0_TWR: J16.A44(UART1_TX) J18.1(A1) R65.1 R88.2
PTE0_TWRPI: J9.8(B4) J18.3(C1)
PTE1: J11.20(B10) J18.5(B2) U3.16(PTE1/LLWU_P0/MADC0_SE11/SPI1_SO)
PTE1_TWR: J16.A43(UART1_RX) J18.4(A2) R62.2 R89.2
PTE1_TWRPI: J9.12(B6) J18.6(C2) R60.1
PTE2: J11.18(B9) J18.8(B3) U3.17(PTE2/LLWU_P1/MADC0_DP1/SPI1_SCK)
PTE2_TWR: J16.A9(GPIO9/UART1_CTS) J18.7(A3) R59.2 R90.2
PTE2_TWRPI: J9.17(A9) J18.9(C3) R23.2
PTE3: J11.16(B8) J18.11(B4) U3.18(PTE3/MADC0_DM1/SPI1_SIN/U\A\R\T)
PTE3_TWR: J16.B21(GPIO1/UART1_RTS) J18.10(A4) R61.2 R91.2
PTE3_TWRPI: J9.18(B9) J18.12(C4) R24.2 R63.1
PTE4: J11.14(B7) R566.2 U3.19(PTE4/LLWU_P2/SPI1_PCS0/UART3_TX)
PTE16/UART2_TX: J10.18(B9) J16.C42(UART2_TXD/TSI1) R84.1
PTE16/UART2_TX/USB_DP: C48.1 R34.2 R84.2 U3.21(PTE16/ADC0_SE4A/SPI0_PCS0/UART2)
PTE17/UART2_RX: J10.17(A9) J16.C41(UART2_RXD/TSI0) R85.1
PTE17/UART2_RX/USB_DN: C35.1 R33.2 R85.2 U3.22(PTE17/ADC0_SE5A/SPI0_SCK/UART2_)
PTE18/UART2_CTS: J10.19(A10) J16.C44(UART2_CTS/TSI3) R86.1
PTE18/UART2_CTS/VOUT33: C27.1 C28.1 D14.A R86.2 U3.23(PTE18/ADC0_SE6A/SPI0_SOUT/U\A\R)
PTE19/UART2_RTS: J10.20(B10) J16.C43(UART2_RTS/TSI2) R87.1
PTE19/UART2_RTS/VREGIN: J27.2 R87.2 U3.24(PTE19/ADC0_SE7A/SPI0_SIN/U\A\R\)
RESET_B: R94.2 U14.3(A)
RF_50: C17.1 C18.2 C19.1 L5.1 Z1.1(UNBAL1)
RF_ANT: ANT1.1(SIGNAL) C18.1
RST_TGTMCU_B: C29.1 D9.C(CATHODE) J9.20(B10) J11.10(B5) J29.1 R560.2 R561.2 SW6.1 SW6.2 U3.41(R\E\S\E\T\)
RSTR: D9.A(ANODE) R46.2
SDA_EXTAL: C31.1 U6.17(EXTAL0/PTA18/FTM0_FLT2/FTM_CLKI) Y3.3
SDA_JTAG_TCLK: J13.4(B2) TP509.1(PIN1) U6.12(JTAG_TCLK/SWD_CLK/EZP_CLK/TSI0_)
SDA_JTAG_TDI: J13.8(B4) TP511.1(PIN1) U6.13(JTAG_TDI/EZP_DI/TSI0_CH2/PTA1/U)
SDA_JTAG_TDO: J13.6(B3) TP510.1(PIN1) U6.14(JTAG_TDO/TRACE_SWO/EZP_DO/TSI0_)
SDA_JTAG_TMS: J13.2(B1) R107.2 TP508.1(PIN1) U6.15(JTAG_TMS/SWD_DIO/TSI0_CH4/PTA3/)
SDA_LED: D11.C(CATHODE) TP106.1(PIN1) U6.29(PTD4/SPI0_PCS1/U\A\R\T\0\_\R\T\)
SDA_LED_R: D11.A(ANODE) R104.2
SDA_RST: J13.10(B5) R52.2 R100.1 TP105.1(PIN1) TP512.1(PIN1) U6.19(R\E\S\E\T\)
SDA_SPI0_SCK: U4.12(4A) U6.26(PTC5/SPI0_SCK/LPTMR0_ALT2/I2S0_)
SDA_SPI0_SIN: R112.1 U4.8(3Y) U6.28(CMP0_IN1/PTC7/SPI0_SIN/USB_SOF_)
SDA_SPI0_SOUT: U4.2(1A) U6.27(CMP0_IN0/PTC6/SPI0_SOUT/PDB0_EX)
SDA_SWD_EN: R106.2 U4.10(O\E\3\) U4.13(O\E\4\) U6.16(N\M\I\/E\Z\P\_\C\S\/TSI0_CH5/PT)
SDA_SWD_OE_B: R105.1 U4.1(O\E\1\) U6.20(ADC0_SE8/TSI0_CH0/PTB0/I2C0_SCL)
SDA_USB_CONN_DN: J15.2(P2) R50.1 U8.1(CATHODE1)
SDA_USB_CONN_DP: J15.3(P3) R51.1 U8.2(CATHODE2)
SDA_USB_DN: R50.2 U6.4(USB0_DM)
SDA_USB_DP: R51.2 U6.3(USB0_DP)
SDA_USB_VOUT33: C26.1 C32.1 D16.A(ANODE) J13.1(A1) R104.1 R105.2 R106.1 R107.1 R110.1 TP103.1(PIN1) U4.4(O\E\2\) U4.14(VCC) U6.1(VDD1) U6.5(VOUT33) U6.7(VDDA) U6.11(VBAT)
SDA_USBSHIELD: J15.S1(SHLD1) J15.S2(SHLD2) J15.S3(SHLD3) J15.S4(SHLD4) L7.1
SDA_XTAL: C30.1 U6.18(XTAL0/PTA19/FTM1_FLT0/FTM_CLKIN) Y3.1
SWD_CLK_TGTMCU: R93.1 U4.11(4Y)
SWD_DIO_TGTMCU: R92.1 U4.3(1Y) U4.9(3A)
TC_74125_SPARE_I_TP: R95.2 TP107.1(PIN1) U4.5(2A)
TC_74125_SPARE_O_TP: TP108.1(PIN1) U4.6(2Y)
TC_EXTAL_TP: TP102.1(PIN1) U6.10(EXTAL32)
TC_SDA_USB_ID_TP: J15.4(P4) TP100.1(PIN1)
TC_XTAL_TP: TP101.1(PIN1) U6.9(XTAL32)
TGT_PWR: J11.11(A6) J11.13(A7) J12.1
UART1_CTS_TGTMCU: R90.1 U6.22(ADC0_SE15/TSI0_CH14/PTC1/SPI0_P)
UART1_RST_TGTMCU: R91.1 U6.23(ADC0_SE4B/CMP1_IN0/TSI0_CH15/PT)
UART1_RX_TGTMCU: R89.1 U6.25(PTC4/SPI0_PCS0/UART1_TX/FTM0_CH)
UART1_TX_TGTMCU: R88.1 U6.24(CMP1_IN1/PTC3/SPI0_PCS1/UART1_R)
V_EXT: J28.1 Q1.2(SOURCE)
V_LED: D4.A(ANODE) D5.A(ANODE) D6.A(ANODE) D7.A(ANODE) D8.A(ANODE) R4.2 R46.1 TP4.1(PIN1)
V_MAIN: D1.C D3.C SW5.1 TP1.1(PIN1)
V_MCU: C7.1 C8.1 C9.1 C13.1 C14.1 C46.1 C47.1 J8.1 J11.1(A1) L2.2 R6.2 R12.1 R20.2 R21.1 R22.1 R23.1 R24.1 R25.2 R26.1 R552.1 R553.1 R554.1 R555.1 R560.1 R563.2 R565.2 TP6.1(PIN1) TP502.1(PIN1) U3.20(VDD_MCU#20) U3.25(VDDA) U3.32(VBAT_MCU) U3.38(VDD_MCU#38) U13.6(VCC) U14.6(VCCB)
V_REG: C2.1 C3.1 D2.A R2.1 TP3.1(PIN1) U1.1(VOUT)
V_RF: C10.1 C11.1 C12.1 R8.2 TP7.1(PIN1) U3.42(VBAT2_RF) U3.55(VBAT_RF)
VOUT33: J3.3 SW5.5
VOUT33_SW: D14.C SW5.6
VREG_IN: C1.1 R1.1 SW5.2 TP2.1(PIN1) U1.5(VIN)
VTRG_EN: Q2.3(COLLECTOR) R108.2 R109.1 R551.2 U7.3(ENABLE)
VTRG_FAULT_B: R110.2 U6.32(PTD7/CMT_IRO/UART0_TX/FTM0_CH7/) U7.4(F\A\U\L\T\)
XTAL_32: C24.1 U3.30(XTAL32) Y2.2
XTAL_32M: R15.1 U3.56(XTAL_32M)
XTAL_32M_R: C22.1 R15.2 Y1.3
Z_RF_N: C25.2 R14.2 Z1.3(BAL3)
Z_RF_P: C25.1 R13.2 Z1.4(BAL4)
N23265787: D4.C(CATHODE) R10.1
N23279171: D5.C(CATHODE) R16.1 TP14.1(PIN1)
N23279177: D6.C(CATHODE) R17.1 TP15.1(PIN1)
N23279197: D8.C(CATHODE) R19.1 TP17.1(PIN1)
N23279203: D7.C(CATHODE) R18.1 TP16.1(PIN1)
N23310364: R78.2 U3.4(PTC4/LLWU_P8/SPI0_PCS0/UART1_TX)
N23310371: R79.2 U3.5(PTC5/LLWU_P9/SPI0_SCK/LPTMR0_AL)
N23310378: R80.2 U3.6(PTC6/LLWU_P10/CMP0_IN0/SPI0_SOU)
N23310385: R81.2 U3.7(PTC7/CMP0_IN1/SPI0_SIN/USB_SOF_)
N23310563: J16.A37(PWM3) J16.A69(EBI_AD11) R66.1
N23310622: J16.A24(I2S0_DIN0) J16.A70(EBI_AD10) R67.1
N23310905: J16.A58(I2S0_DIN_SCK) J16.A71(EBI_AD9) R68.1
N23310921: J16.A59(I2S0_DIN_WS) J16.A72(EBI_AD8) R69.1
N23313140: J16.A76(EBI_AD4) R77.1
N23313187: J16.A77(EBI_AD3) R75.1
N23313323: J16.B38(PWM6) R64.2
N23325134: J16.B23(GPIO3) J16.B25(CLKOUT1) R65.2
N23327200: R12.2 U3.29(TAMPER0/R\T\C\_\W\A\K\E\U\P\)
N23340195: L3.1 U3.27(VREFL)
N23345722: R14.1 U3.50(RF_OUTN)
N23346446: R13.1 U3.49(RF_OUTP)
N23353475: C20.1 J5.1
N23360966: C36.1 L2.1 U3.26(VREFH)
N23363687: J16.B27(AN7) R58.2
N23363690: J16.B28(AN6) R60.2
N23363940: J16.A27(AN3) R59.1
N23363943: J16.A28(AN2) R61.1
N23364230: J16.A29(AN1) R62.1
N23364481: J16.B71(EBI_R/W\) R74.2
N23364514: J16.B67(EBI_AD16) R70.2
N23364562: J16.B68(EBI_AD17) R71.2
N23364605: J16.B70(EBI_AD19) R73.2
N23364648: J16.B69(EBI_AD18) R72.2
N23364699: J16.B30(AN4) R63.2
N23366702: TP26.1(PIN1) U3.46(RX_SWITCH)
N23421288: J16.A75(EBI_AD5) R76.1
N23440330: TP21.1(PIN1) U3.44(ANT_A)
N23440333: TP22.1(PIN1) U3.45(ANT_B)
N23460837: C45.1 Z1.2(UNBAL2)
N23503244: C17.2 J4.1(CENTER)
N23570419: D15.A L4.2
N23642836: C4.1 R1.2 U1.6(EN) U1.7(PS/SYNC) U1.8(VINA)
N23642972: L1.2 U1.2(L2)
N23642976: L1.1 U1.4(L1)
N23643006: R2.2 R5.1 U1.10(FB)
N23643076: Q1.1(GATE) R7.2 R9.1
N23643080: D3.A Q1.3(DRAIN)
N23643183: D2.C J3.1
N23643259: J2.2(B1) R4.1
N23643265: J2.4(B2) R6.1
N23643271: J2.6(B3) R8.1
N23643416: D1.A J1.2(B1) J1.4(B2) J1.6(B3) R7.1
N23645388: R563.1 R564.1 U13.3(R\E\S\E\T\)
N23645400: R565.1 R566.1 U13.5(W\P\)
N23647269: D16.C(CATHODE) R562.1 U14.1(VCCA) U14.5(OE)
N23647277: J30.2 R94.1 U6.21(ADC0_SE9/TSI0_CH6/PTB1/I2C0_SDA)
N23648037: C34.2 U7.5(CSLEW)
N23648090: Q2.1(BASE) R111.2
N23648321: D13.A L6.2
N23648566: J29.2 U14.4(B)
N23649169: J16.A63(R\S\T\O\U\T\) R561.1
N23664400: TP25.1(PIN1) U3.47(TX_SWITCH)

Pads without a net: J6 4; J13 7 9; J16 A10 A11 A12 A13 A14 A15 A16 A17 A18 A19 A20 A21 A22 A23 A25 A30 A32 A33 A34 A35 A38 A39 A40 A47 A48 A50 A51 A52 A54 A55 A56 A57 A61 A62 A64 A66 A67 A68 A73 A74 B8 B12 B13 B14 B15 B16 B17 B18 B19 B20 B22 B24 B29 B32 B33 B34 B35 B37 B39 B40 B41 B42 B43 B50 B51 B53 B54 B55 B56 B57 B58 B59 B60 B61 B62 B64 B66 B72 B73 B74 B75 B76 B77 B78 B79 B80 C7 C8 C9 C10 C11 C12 C13 C14 C15 C16 C17 C18 C19 C20 C21 C22 C23 C24 C25 C27 C28 C29 C30 C32 C33 C34 C35 C37 C38 C39 C40 C45 C46 C47 C48 C50 C51 C52 C53 C54 C55 C56 C57 C58 C59 C60 C61 C62 C63 C64 C66 C67 C68 C69 C70 C71 C72 C73 C74 C75 C76 C77 C78 C79 C80 D7 D8 D9 D10 D11 D12 D13 D14 D15 D16 D17 D18 D19 D20 D21 D22 D23 D24 D25 D27 D28 D29 D30 D32 D33 D34 D35 D37 D38 D39 D40 D41 D42 D43 D44 D45 D46 D47 D48 D52 D53 D54 D55 D56 D57 D58 D59 D60 D61 D62 D63 D64 D66 D67 D68 D69 D70 D71 D72 D73 D74 D75 D76 D77 D78 D79 D80; SW5 3 4; U3 57 58 59 60 61 62; U6 30; Z1 6

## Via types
v1: diameter 0.457, hole 0.178, TOP to BOTTOM, 76 vias
v2: diameter 0.457, hole 0.203, TOP to BOTTOM, 869 vias

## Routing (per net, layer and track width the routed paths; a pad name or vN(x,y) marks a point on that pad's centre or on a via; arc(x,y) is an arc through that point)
3V3_ELEV: length 91.7
  TOP w0.178: J16.A3 84.48,73.23 v2(84.51,73.2) ; J16.A36 49.48,70.51 v1(49.61,70.38)
  TOP w0.508: J16.C36 v2(40.48,7.85) ; v2(4.14,68.38) 4.14,71.68 3.48,72.34 J16.A82 ; J16.C82 86.48,6.51 v2(84.71,8.28) ; v2(6.58,7.62) 6.58,7.65 5.48,6.55 J16.C3
  L3_PWR w0.178: 77.5,68.78 81.28,72.57 83.87,72.57 v2(84.51,73.2)
  L3_PWR w0.508: 77.29,8.38 84.61,8.38 v2(84.71,8.28) ; J1.3 15.77,19.41 15.77,15.09
  BOTTOM w0.178: J16.A3 84.48,73.23 v2(84.51,73.2) ; v1(49.61,70.38) 49.48,70.51 J16.A36
  BOTTOM w0.508: v2(84.71,8.28) 86.48,6.51 J16.C82 ; v2(6.58,7.62) 6.58,7.65 5.48,6.55 J16.C3 J16.C4 ; J16.C36 v2(40.48,7.85) ; J16.A4 J16.A3 ; J16.A82 3.48,72.34 4.14,71.68 v2(4.14,68.38)
5V_ELEV: length 199.8
  TOP w0.178: v2(78.46,67.41) 78.46,69.27 81.23,72.03 85.42,72.03 86.48,73.09 J16.B1 ; J9.1 v2(73.18,56.95)
  TOP w0.508: J16.D1 v2(3.48,6.68)
  L3_PWR w0.178: v2(75.23,62.51) 75.87,62.51 78.46,65.1 v2(78.46,67.41) ; v2(75.23,62.51) v1(48.62,62.51) 28.45,62.51 27.28,61.34 v1(3.43,61.34) 4.17,60.6 4.17,33.66 7.47,30.35 7.47,26.87 ; v2(75.23,62.51) 75.23,57.94 74.24,56.95 v2(73.18,56.95)
  L3_PWR w0.508: J1.5 11.96,18.14 7.47,22.63 7.47,26.87
  BOTTOM w0.508: J1.5 14.46,18.09 D12.C 11.25,15.85 5.38,15.85 3.76,14.22 3.76,6.96 v2(3.48,6.68) J16.C1 ; v2(78.46,67.41) 78.89,67.84 78.89,69.9 80.98,71.98 85.67,71.98 86.48,72.79 J16.A1
GND: length 528.5
  TOP w0.178: v2(29.49,12.93) 29.17,12.61 U1.9 ; 52.37,73.28 54.48,75.39 J16.A31 ; U3.48 68.03,27.06 68.02,27.05 ; 36.48,72.58 J16.A49 ; C43.2 71.65,30.45 v2(72.34,30.45) ; C44.2 71.3,29.44 71.45,29.59 72.31,29.59 v2(72.31,29.62) ; U3.51 68.01,28.56 68,28.57 ; v2(59.79,23.75) 60.6,24.56 61.1,24.56 U3.28
  TOP w0.305: Z1.5 v2(74.9,26.16)
  TOP w0.33: 23.65,12.52 24.06,12.11 U1.3 ; C42.2 72.16,31.37
  TOP w0.508: 14.36,45.19 R10.2 ; R10.2 15.46,45.19 ; R10.2 14.91,44.64 ; J16.C2 4.48,6.57 6.38,8.46 ; 21.35,49.2 SW6.4 ; SW6.4 22.66,48.34 ; SW6.4 23.97,49.2 ; SW6.4 22.66,50.06 ; 26.7,9.98 U1.11 ; U1.11 27.75,9.98 ; U1.11 26.7,15.34 v2(26.7,15.34) ; 37.36,36.09 J13.3 37.36,36.32 ; 65.84,59.19 J9.6 65.84,59.49 ; SW4.2 51.43,21.86 ; SW4.2 51.43,19.24 ; SW4.2 52.3,20.55 ; SW4.2 50.57,20.55 ; 55.68,64.27 J10.14 55.68,64.57 ; TL2.1 36.58,56.41 ; TL2.1 34.63,55.3 ; TL2.1 38.52,55.3 ; TL2.1 36.58,54.18 ; 5.18,49.89 J11.15 5.18,50.18 ; 23.51,10.54 22.41,10.54 ; 65.84,62.03 J9.10 65.84,61.73 ; C29.2 25.22,48.22 ; C29.2 25.77,47.68 ; C29.2 24.68,47.68 ; J15.5 10.76,37.26 ; J15.5 8.02,37.26 ; J15.5 9.39,36.78 ; C1.2 16.71,9.65 17.25,9.12 v2(18.75,9.12) ; C7.2 57.91,33.34 ; C7.2 58.46,32.79 ; C7.2 57.37,32.79 ; J16.A26 59.48,73.43 v2(59.11,73.05) ; R5.2 23.17,23.32 ; R5.2 22.19,22.89 ; R5.2 22.73,23.88 ; J28.2 27.93,37.43 ; J28.2 27.93,35.93 ; J28.2 26.43,35.93 ; J28.2 26.43,37.43 ; 70.42,36.19 Y1.2 ; Y1.2 69.49,37.02 ; Y1.2 71.34,37.02 ; 14.91,25.03 C50.2 ; C50.2 14.91,26.12 ; C50.2 15.46,25.58 ; C3.2 25.22,25.54 ; C3.2 26.21,24.87 ; C3.2 24.23,24.87 ; 67.44,19.8 C46.2 ; C46.2 66.89,20.35 ; C46.2 67.98,20.35 ; SW2.1 52.27,44.6 ; SW2.1 51.41,43.29 ; SW2.1 51.41,45.91 ; 62.72,38.59 J5.2 ; J5.2 64.23,40.1 ; J5.2 64.23,38.59 ; J5.2 62.72,40.1 ; 68.88,19.21 C14.2 ; C14.2 69.43,19.76 ; C14.2 68.34,19.76 ; 18.94,22.94 R9.2 ; R9.2 19.48,22.39 ; R9.2 20.03,22.94 ; J16.A6 J16.A5 82.48,73.77 v2(81.74,73.03) ; 26.2,46.66 R95.1 ; R95.1 26.75,46.11 ; R95.1 27.29,46.66 ; SW3.1 51.43,37 ; SW3.1 52.3,35.69 ; SW3.1 50.57,35.69 ; SW3.1 51.43,34.38 ; 16.36,39.4 U8.3 ; U8.3 17.03,38.77 ; U8.3 17.03,40.02 ; U8.3 17.7,39.4 ; 62.48,64.57 J10.13 62.48,64.87 ; v2(81.74,73.03) 82.25,72.52 84.76,72.52 85.48,73.24 J16.A2 ; v2(81.74,73.03) 81,73.03 ; 19.51,41.95 C49.2 ; C49.2 20.05,42.49 ; C49.2 18.96,42.49 ; 62.48,59.79 J10.5 62.48,59.49 ; SW2.2 52.27,40.79 ; SW2.2 51.41,42.1 ; SW2.2 51.41,39.48 ; v2(10.6,7.97) 8.48,5.86 J16.C6 J16.C5 ; C12.2 74.11,32.31 ; C12.2 73.56,32.86 ; C12.2 73.56,31.76 ; 60.79,56.35 J10.1 62.48,56.95 ; 55.68,60.46 J10.8 55.68,60.76 ; C45.2 75.45,30.76 ; C45.2 74.9,31.31 ; C45.2 74.36,30.76 ; C13.2 58.15,16.97 ; C13.2 57.61,16.42 ; C13.2 57.61,17.51 ; 72.64,58.22 J9.3 72.64,58.52 ; 5.66,72.75 4.48,73.93 J16.B81 ; 24.32,41.87 TP507.1 ; TP507.1 24.32,39.81 ; TP507.1 26.38,41.87 ; TP507.1 26.38,39.81 ; 62.48,61.06 J10.7 62.48,60.76 ; SW1.1 52.3,52.27 ; SW1.1 51.43,53.58 ; SW1.1 51.43,50.96 ; 18.62,54.46 J30.1 ; J30.1 18.62,52.48 ; J30.1 20.6,54.46 ; J30.1 20.6,52.48 ; 70.97,23 C15.2 ; C15.2 71.96,23.55 ; C15.2 70.66,23.24 ; C15.2 71.4,23.11 ; SW3.2 52.3,31.88 ; SW3.2 51.43,30.57 ; SW3.2 50.57,31.88 ; SW3.2 51.43,33.19 ; 65.84,64.57 J9.14 65.84,64.27 ; C22.2 71.91,40.17 ; C22.2 71.36,39.62 ; C22.2 72.45,39.62 ; 57.37,56.35 J10.2 55.68,56.95 ; J16.C65 69.48,7.99 69.47,8 ; 66.19,20.46 C47.2 65.65,21.01 ; L8.2 12.13,16.9 ; L8.2 13.01,15.93 ; L8.2 12.13,14.95 ; L8.2 11.25,15.93 ; 8.65,18.52 U11.2 ; U11.2 9.33,19.1 ; U11.2 8.65,19.68 ; C2.2 27.46,25.57 ; C2.2 28.45,24.89 ; C2.2 26.47,24.89 ; 2.74,55.64 J11.5 ; J11.5 3.56,55.64 ; J11.5 J11.3 ; 51.43,23.05 SW4.1 ; SW4.1 52.3,24.36 ; SW4.1 51.43,25.67 ; SW4.1 50.57,24.36 ; 50.57,48.46 SW1.2 ; SW1.2 51.43,47.15 ; SW1.2 52.3,48.46 ; SW1.2 51.43,49.77 ; U12.2 9.33,17.6 ; U12.2 8.65,18.18 ; U12.2 8.65,17.02 ; 65.84,65.54 J9.16 65.84,65.84 ; 37.36,37.36 J13.5 37.36,37.59 ; 65.98,39.5 C21.2 ; C21.2 67.07,39.5 ; C21.2 66.52,40.04 ; 57.2,26.86 C36.2 56.76,26.75 ; L7.2 14.11,35.4 ; L7.2 13.23,34.42 ; L7.2 14.99,34.42 ; L7.2 14.11,33.44 ; 87.56,56.36 J4.4 ; J4.4 84.89,57.42 ; J4.4 87.56,58.47 ; 25.04,27.3 TL3.1 ; TL3.1 25.04,29.54 ; TL3.1 23.1,28.42 ; TL3.1 26.99,28.42 ; TL1.1 57.58,49.16 ; TL1.1 57.58,45.27 ; TL1.1 58.7,47.22 ; TL1.1 56.46,47.22 ; 18.85,48.34 SW6.3 ; SW6.3 17.54,49.2 ; SW6.3 20.16,49.2 ; SW6.3 18.85,50.06 ; 59.51,30.34 C8.2 59.07,30.23 ; 20.48,73.19 J16.A65 ; 67.29,38.62 Y1.4 ; Y1.4 69.14,38.62 ; Y1.4 68.22,39.45 ; U10.2 8.65,21.18 ; U10.2 8.65,20.02 ; U10.2 9.33,20.6 ; 55.68,59.19 J10.6 55.68,59.49 ; 84.89,65.93 J4.2 ; J4.2 87.56,64.87 ; J4.2 87.56,67.23 ; 72.64,64.57 J9.13 72.64,64.87 ; 72.64,60.76 J9.7 72.64,61.06 ; 72.64,63.3 J9.11 72.64,63.6 ; 72.64,59.79 J9.5 72.64,59.49 ; 78.56,7.75 78.59,7.72 83.41,7.72 85.48,5.65 J16.D81 ; 58.73,30.23 C9.2 58.29,30.34 ; 3.56,46.75 J11.19 5.18,47.35 ; C19.2 v2(76.68,30.51) ; J16.C26 30.48,7.74 30.48,7.75 ; 56.16,23.65 L3.2 56.83,22.85 ; 60,21.41 C24.2 59.56,21.3 ; 70.95,68.97 J9.19 72.64,68.38 ; 35.48,7.7 J16.C31 ; 5.18,48.91 J11.17 5.18,48.62 ; 63.07,18.86 C23.2 63.61,19.41 ; 72.64,66.14 J9.15 72.64,65.84 ; 53.49,7.85 53.48,7.84 J16.C49 ; J6.5 5.38,17.78 ; U13.7 63.76,46.08 ; U13.7 62.73,45.54 ; U13.7 62.73,46.61 ; L5.2 v2(77.9,30.51)
  L2_GND w0.508: J30.1 20.36,54.22 ; J30.1 18.86,52.72 ; J30.1 20.36,52.72 ; J30.1 18.86,54.22 ; 37.36,36.32 J13.3 37.36,36.09 ; TP507.1 26.38,39.81 ; TP507.1 24.32,39.81 ; TP507.1 26.38,41.87 ; TP507.1 24.32,41.87 ; J5.2 64.23,40.1 ; J5.2 62.72,38.59 ; J5.2 64.23,38.59 ; J5.2 62.72,40.1 ; 26.43,35.93 J28.2 ; J28.2 27.93,35.93 ; J28.2 26.43,37.43 ; J28.2 27.93,37.43 ; 80.71,23.01 ANT1.2 80.71,21.91 ; 37.36,37.36 J13.5 37.36,37.59
  BOTTOM w0.178: J16.A6 81.48,73.28 v2(81.74,73.03) 82.17,72.59 84.89,72.59 85.48,73.19 J16.A2 ; 36.07,42.11 U6.8 36.07,43.38 v2(37.82,45.14) 37.87,45.14 39.07,43.94 U6.2 39.07,42.12
  BOTTOM w0.508: J30.1 20.6,52.48 ; J30.1 20.6,54.46 ; J30.1 18.62,54.46 ; J30.1 18.62,52.48 ; 62.72,40.1 J5.2 ; J5.2 62.72,38.59 ; J5.2 64.23,40.1 ; J5.2 64.23,38.59 ; 47.35,37.63 R112.2 47.89,38.18 ; 84.89,57.42 J4.4 ; J4.4 87.56,56.36 ; J4.4 87.56,58.47 ; R562.2 15.32,45.83 ; R562.2 15.32,44.74 ; R562.2 14.77,45.29 ; 54.48,73.2 J16.A31 ; C26.2 34.85,32.86 ; C26.2 34.3,32.31 ; C26.2 35.4,32.31 ; 78.69,7.7 83.93,7.7 85.48,6.15 J16.C81 ; 41.22,30.97 R109.2 ; R109.2 41.77,31.52 ; R109.2 40.68,31.52 ; 34.77,48.86 C31.2 ; C31.2 34.77,49.95 ; C31.2 34.23,49.4 ; 43.46,28.93 Q2.2 ; Q2.2 44.07,29.77 ; Q2.2 44.68,28.93 ; Q2.2 44.07,28.09 ; J4.2 87.56,66.98 ; J4.2 87.56,64.87 ; J4.2 84.89,65.93 ; 57.89,41.33 TP12.1 ; TP12.1 57.15,42.06 ; TP12.1 57.89,42.8 ; TP12.1 58.62,42.06 ; 41.17,37.16 U7.2 41.17,35.48 ; 45.39,34.81 C33.2 ; C33.2 45.94,35.36 ; C33.2 45.39,35.9 ; 31.24,33.41 R100.2 ; R100.2 30.44,34.09 ; R100.2 32.04,34.09 ; 56.35,28.57 C35.2 55.26,28.57 ; J16.C2 4.48,6.54 5.77,7.82 ; C28.2 57.12,54.75 ; C28.2 57.12,53.66 ; C28.2 56.58,54.2 ; 35.61,7.75 35.61,7.75 ; v2(30.48,9.01) J16.C26 ; J16.A6 J16.A5 ; 55.65,23.68 C48.2 ; C48.2 56.2,24.23 ; C48.2 55.1,24.23 ; 56.62,51.8 C27.2 ; C27.2 56.62,53.4 ; C27.2 55.94,52.6 ; Y3.4 36.35,55.16 ; Y3.4 35.43,54.01 ; Y3.4 35.43,56.32 ; Y3.4 34.5,55.16 ; J16.A49 36.48,73.19 ; 53.42,67.64 TP9.1 52.68,66.9 ; 38.75,51.26 Y3.2 37.83,52.42 ; 26.14,12.55 TP11.1 ; TP11.1 26.95,12.62 29.18,12.62 v2(29.49,12.93) ; TP11.1 27.61,12.55 ; TP11.1 26.87,13.28 ; TP11.1 26.87,11.81 ; 26.43,35.93 J28.2 ; J28.2 27.93,37.43 ; J28.2 27.93,35.93 ; J28.2 26.43,37.43 ; TP507.1 26.38,39.81 ; TP507.1 24.32,39.81 ; TP507.1 24.32,41.87 ; TP507.1 26.38,41.87 ; v2(52.12,7.87) 53.48,6.51 J16.C49 ; J16.C65 69.48,6.84 v2(68.17,8.15) ; 37.36,37.59 J13.5 37.36,37.36 ; 38.55,49.4 C30.2 38.44,49.84 ; TP10.1 57.84,67.56 ; TP10.1 57.1,68.3 ; TP10.1 57.1,66.83 ; TP10.1 56.36,67.56 ; J16.A26 59.48,73.43 v2(59.11,73.05) ; 35.7,32.82 C32.2 ; C32.2 37.3,32.82 ; C32.2 36.5,33.49 ; v2(10.6,7.97) 8.48,5.86 J16.C6 J16.C5 ; U4.7 47.57,48.2 ; U4.7 47.14,49.2 ; U4.7 47.14,47.21 ; J16.A81 4.48,73.37 5.46,72.39 v2(6.71,72.39) ; 37.36,36.09 J13.3 37.36,36.32 ; J16.C31 35.48,6.43 v2(36.91,7.85) ; 20.48,73.14 J16.A65 ; 17.27,41.76 U14.2 17.27,43.33
  vias: v1(3.17,54.99) v1(62.48,28.8) v1(62.48,26.29) v1(62.92,30.18) v1(63.17,25.5) v1(63.7,27.53) v1(64.16,29.69) v1(64.31,25.5) v1(64.87,28.8) v1(64.89,26.24) v1(65.38,30.18) v1(65.63,27.76) v1(66.39,28.78) v1(66.39,26.87) v1(66.88,30.18) v1(66.9,27.74) v1(67.51,28.78) v1(67.51,26.87) v2(3.15,44.88) v2(4.39,13.59) v2(5.44,62.26) v2(5.41,14.94) v2(5.64,23.09) v2(7.7,31.9) v2(8.03,7.65) v2(8.23,62.26) v2(9.3,8.94) v2(10.59,9.83) v2(10.95,13.34) v2(11.15,11.25) v2(12.07,12.12) v2(12.01,10.52) v2(12.5,69.22) v2(13.23,11.02) v2(14.1,69.14) v2(15.42,66.62) v2(19.74,8.79) v2(19.68,7.82) v2(20.29,9.96) v2(21.26,71.91) v2(21.18,8.81) v2(21.46,7.85) v2(21.84,55.19) v2(21.97,62.53) v2(23.6,7.85) v2(24.03,55.14) v2(24.05,53.85) v2(25.25,68.48) v2(25.22,67.41) v2(25.17,53.52) v2(25.3,52.63) v2(25.53,7.85) v2(25.88,53.77) v2(26.8,52.53) v2(27.1,7.85) v2(28.4,72.47) v2(29.01,7.85) v2(29.16,8.71) v2(30,72.47) v2(30.96,42.88) v2(31.17,72.44) v2(31.37,69.49) v2(31.45,23.24) v2(32.18,72.44) v2(32.38,55.58) v2(32.56,9.07) v2(33.07,22.61) v2(33.4,7.85) v2(33.81,29.24) v2(34.49,9.07) v2(35.51,14.38) v2(36.07,9.07) v2(37.13,16.51) v2(37.54,22.61) v2(37.69,15.47) v2(37.97,9.07) v2(38.68,20.04) v2(38.81,7.85) v2(39.75,9.02) v2(40.97,53.04) v2(42.16,34.85) v2(42.8,7.85) v2(43.66,12.01) v2(44.07,30.33) v2(44.58,7.87) v2(44.98,34.42) v2(48.64,7.87) v2(50.22,7.87) v2(50.55,71.91) v2(50.52,16.03) v2(51.16,33.81) v2(51.21,7.9) v2(51.79,16.05) v2(52.58,9.12) v2(52.68,67.59) v2(54,9.12) v2(55.17,9.3) v2(55.4,7.98) v2(55.98,23.32) v2(56.39,14.05) v2(56.64,9.02) v2(57.15,40.84) v2(57.89,34.16) v2(58.14,9.22) v2(58.14,8.23) v2(58.29,30.86) v2(58.39,44.02) v2(58.57,35.13) v2(58.57,32.44) v2(59.39,30.89) v2(59.64,20.57) v2(59.59,19.79) v2(60.32,35.13) v2(60.4,21.26) v2(60.71,34.47) v2(61.04,8.23) v2(62.53,72.92) v2(62.84,41.22) v2(63.58,8.18) v2(63.91,46.81) v2(63.91,45.39) v2(64.24,18.95) v2(64.34,21.08) v2(64.39,46.13) v2(64.52,41.2) v2(65.2,21.06) v2(66.17,8.18) v2(66.78,19.08) v2(67.79,19.33) v2(68.35,41.38) v2(68.4,40.21) v2(68.76,53.26) v2(68.68,43.03) v2(69.37,17.4) v2(69.8,43.61) v2(69.82,22.3) v2(69.9,42.14) v2(69.9,40.74) v2(70.03,19.53) v2(70.13,45.36) v2(70.18,52.86) v2(70.18,35.31) v2(70.36,50.7) v2(70.28,47.98) v2(70.36,46.74) v2(70.31,34.01) v2(70.56,40.06) v2(71.22,49.71) v2(71.17,35.48) v2(71.22,8.08) v2(71.3,34.04) v2(71.48,51.77) v2(71.48,40.67) v2(72.06,43.61) v2(72.16,52.5) v2(72.16,50.83) v2(72.16,49.56) v2(72.09,41.15) v2(72.11,22.3) v2(72.11,21.29) v2(72.19,45.62) v2(72.36,47.88) v2(72.29,41.94) v2(73.05,30.56) v2(73.03,29.69) v2(73.05,24.92) v2(73.05,23.6) v2(73.08,26.09) v2(73.08,21.97) v2(73.08,20.22) v2(73.43,8.08) v2(73.53,53.64) v2(73.56,33.5) v2(73.61,51.74) v2(73.63,48.31) v2(73.66,47.22) v2(73.61,15.21) v2(73.69,49.38) v2(73.84,45.97) v2(74.02,43.31) v2(74.04,40.06) v2(74.09,44.73) v2(74.14,37.49) v2(74.12,35.74) v2(74.14,29.62) v2(74.14,26.01) v2(74.14,24.1) v2(74.14,23.19) v2(74.12,21.89) v2(74.17,20.42) v2(74.14,18.39) v2(74.27,55.22) v2(74.24,53.95) v2(74.22,50.95) v2(74.27,49.89) v2(74.27,47.78) v2(74.19,42.55) v2(74.19,40.82) v2(74.24,39.12) v2(74.19,24.84) v2(74.22,19.58) v2(74.3,52.96) v2(74.3,51.97) v2(74.32,48.9) v2(74.3,46.71) v2(74.55,9.02) v2(74.57,33.93) v2(74.63,32.39) v2(74.73,45.67) v2(74.75,38.28) v2(74.73,36.53) v2(74.75,33.15) v2(74.75,22.58) v2(74.75,20.95) v2(74.75,18.95) v2(74.8,43.33) v2(74.8,41.61) v2(74.85,39.9) v2(74.8,25.35) v2(74.83,20.04) v2(74.85,15.72) v2(74.85,14.55) v2(74.9,31.57) v2(74.93,23.8) v2(74.93,21.67) v2(74.9,17.75) v2(75.06,53.57) v2(74.98,44.73) v2(74.98,34.8) v2(75.11,54.38) v2(75.11,52.63) v2(75.16,51.56) v2(75.11,50.52) v2(75.16,47.68) v2(75.21,49.61) v2(75.18,48.64) v2(75.18,46.71) v2(75.46,42.49) v2(75.46,40.77) v2(75.41,37.44) v2(75.39,35.69) v2(75.39,33.86) v2(75.41,32.44) v2(75.51,39.07) v2(75.62,29.92) v2(75.62,26.06) v2(75.64,24.66) v2(75.59,22.48) v2(75.62,20.78) v2(75.62,18.72) v2(75.64,16.64) v2(75.77,56.85) v2(75.72,45.62) v2(75.77,44.35) v2(75.72,30.76) v2(75.72,7.7) v2(75.87,54.71) v2(75.9,55.65) v2(75.92,53.72) v2(75.92,52.73) v2(75.9,50.65) v2(75.95,49.66) v2(75.9,48.54) v2(75.92,47.47) v2(75.95,33.12) v2(75.95,31.67) v2(76.02,38.3) v2(76,36.55) v2(76,34.72) v2(76.07,57.94) v2(76.12,51.71) v2(76.07,43.36) v2(76.07,41.63) v2(76.12,39.93) v2(76.15,15.72) v2(76.2,26.87) v2(76.25,25.48) v2(76.2,23.83) v2(76.23,23.06) v2(76.23,21.77) v2(76.2,19.69) v2(76.2,17.75) v2(76.45,45.03) v2(76.45,44.15) v2(76.48,59.77) v2(76.56,46.2) v2(76.63,37.44) v2(76.61,35.69) v2(76.61,33.86) v2(76.61,32.44) v2(76.76,56.95) v2(76.71,56.11) v2(76.73,55.14) v2(76.68,54.33) v2(76.73,53.39) v2(76.73,51.28) v2(76.68,42.49) v2(76.68,40.77) v2(76.73,39.07) v2(76.68,9.02) v2(76.84,61.42) v2(76.86,58.01) v2(76.78,52.32) v2(76.84,50.37) v2(76.81,49.4) v2(76.78,48.44) v2(76.81,47.47) v2(76.84,26.34) v2(76.84,24.69) v2(76.86,22.45) v2(76.81,20.75) v2(76.81,18.69) v2(76.84,16.61) v2(77.06,59.03) v2(77.29,34.7) v2(77.32,33.07) v2(77.32,31.78) v2(77.37,26.85) v2(77.32,25.53) v2(77.37,23.8) v2(77.34,15.7) v2(77.39,39.93) v2(77.39,38.25) v2(77.42,36.55) v2(77.44,21.77) v2(77.42,19.69) v2(77.39,17.73) v2(77.55,59.87) v2(77.7,61.01) v2(77.75,35.64) v2(77.75,33.91) v2(77.75,9.78) v2(77.85,24.69) v2(77.77,7.7) v2(77.88,26.34) v2(78.03,39.09) v2(78.03,37.41) v2(77.98,32.44) v2(78.05,22.89) v2(78.03,20.75) v2(78.03,18.69) v2(78.05,16.61) v2(78.05,14.55) v2(78.26,48.41) v2(78.21,9.02) v2(78.36,55.22) v2(78.33,54.43) v2(78.31,53.47) v2(78.28,52.35) v2(78.33,51.36) v2(78.31,50.47) v2(78.31,49.48) v2(78.31,21.79) v2(78.38,57.07) v2(78.41,56.24) v2(78.44,31.04) v2(78.46,26.85) v2(78.46,25.53) v2(78.44,19.69) v2(78.51,61.04) v2(78.56,57.91) v2(78.51,47.04) v2(78.51,45.77) v2(78.51,44.88) v2(78.54,43.92) v2(78.49,42.55) v2(78.51,23.83) v2(78.56,15.7) v2(78.59,38.18) v2(78.59,36.5) v2(78.59,34.62) v2(78.64,33.91) v2(78.66,33.17) v2(78.66,31.8) v2(78.66,29.92) v2(78.61,17.73) v2(78.87,58.57) v2(79.04,26.34) v2(78.99,24.69) v2(79.04,20.75) v2(79.04,18.69) v2(79.1,43.33) v2(79.1,41.63) v2(79.07,22.89) v2(79.07,21.77) v2(79.07,16.61) v2(79.07,14.55) v2(79.35,61.75) v2(79.35,55.17) v2(79.45,56.31) v2(79.43,54.13) v2(79.4,51.13) v2(79.45,50.06) v2(79.45,47.96) v2(79.38,23.83) v2(79.48,59.31) v2(79.48,57.35) v2(79.48,53.14) v2(79.48,52.15) v2(79.5,49.07) v2(79.48,46.89) v2(79.48,45.87) v2(79.48,44.73) v2(79.6,39.98) v2(79.65,26.85) v2(79.58,25.55) v2(79.6,19.71) v2(79.63,17.73) v2(79.58,15.7) v2(79.73,58.19) v2(79.76,42.49) v2(79.76,40.79) v2(79.86,39.09) v2(79.91,37.44) v2(79.91,35.71) v2(80.01,33.81) v2(80.06,29.82) v2(80.06,21.74) v2(80.06,20.75) v2(80.14,60.07) v2(80.11,32.61) v2(80.09,31.45) v2(80.09,30.56) v2(80.14,23.8) v2(80.11,22.91) v2(80.14,9.02) v2(80.21,62.18) v2(80.26,58.88) v2(80.26,55.3) v2(80.24,53.75) v2(80.19,26.34) v2(80.19,24.74) v2(80.29,56.31) v2(80.29,52.81) v2(80.34,51.74) v2(80.29,50.7) v2(80.37,48.82) v2(80.34,47.85) v2(80.37,46.89) v2(80.37,45.87) v2(80.37,44.73) v2(80.37,43.36) v2(80.37,41.66) v2(80.31,18.69) v2(80.34,16.74) v2(80.44,57.28) v2(80.39,49.78) v2(80.47,39.95) v2(80.52,38.3) v2(80.52,36.58) v2(80.65,34.82) v2(80.65,33.22) v2(80.65,32.03) v2(80.75,54.48) v2(80.67,30.99) v2(80.72,25.58) v2(80.77,64.8) v2(80.82,63.83) v2(80.85,60.53) v2(80.8,59.51) v2(80.77,26.85) v2(80.87,62.79) v2(80.9,19.71) v2(80.95,17.63) v2(80.95,15.85) v2(80.98,42.49) v2(80.98,40.79) v2(81,29.79) v2(81.15,56.31) v2(81.1,53.75) v2(81.15,52.76) v2(81.15,51.77) v2(81.08,50.75) v2(81.13,49.68) v2(81.13,47.57) v2(81.15,46.51) v2(81.15,45.49) v2(81.15,44.35) v2(81.08,39.09) v2(81.13,37.44) v2(81.13,35.71) v2(81.13,33.86) v2(81.23,58.65) v2(81.18,48.69) v2(81.25,32.59) v2(81.23,31.52) v2(81.23,30.53) v2(81.23,26.14) v2(81.2,18.8) v2(81.28,57.3) v2(81.28,55.14) v2(81.28,24.77) v2(81.31,23.65) v2(81.28,21.51) v2(81.51,59.97) v2(81.64,64.8) v2(81.69,63.8) v2(81.69,62.81) v2(81.79,60.81) v2(82.65,64.97) v2(82.65,59.36) v2(82.7,63.98) v2(82.7,62.99) v2(82.7,60.93) v2(82.7,58.37) v2(82.7,57.38) v2(83.46,64.59) v2(83.46,58.98) v2(83.52,63.65) v2(83.57,62.59) v2(83.52,59.79) v2(83.52,58.04) v2(83.57,56.97) v2(83.59,60.96) v2(83.97,65.33) v2(84.33,64.59) v2(84.33,59.41) v2(84.38,63.6) v2(84.38,62.61) v2(84.38,60.96) v2(84.38,60.22) v2(84.38,58.47) v2(84.43,57.4) v2(84.43,56.36) v2(84.96,55.83) v2(85.37,62.46) v2(85.37,58.98) v2(85.39,64.36) v2(85.39,60.88) v2(86,67.26) v2(86.03,55.83) v2(86.44,64.36) v2(86.44,62.46) v2(86.44,60.88) v2(86.44,58.98) v2(86.87,67.26) v2(87.07,55.83) v2(87.5,64.36) v2(87.5,62.46) v2(87.5,60.88) v2(87.5,58.98) v2(88.14,55.83) v2(88.29,67.26) v2(88.57,64.36) v2(88.57,62.46) v2(88.57,60.88) v2(88.57,58.98) v2(89.18,67.26) v2(89.2,55.83)
